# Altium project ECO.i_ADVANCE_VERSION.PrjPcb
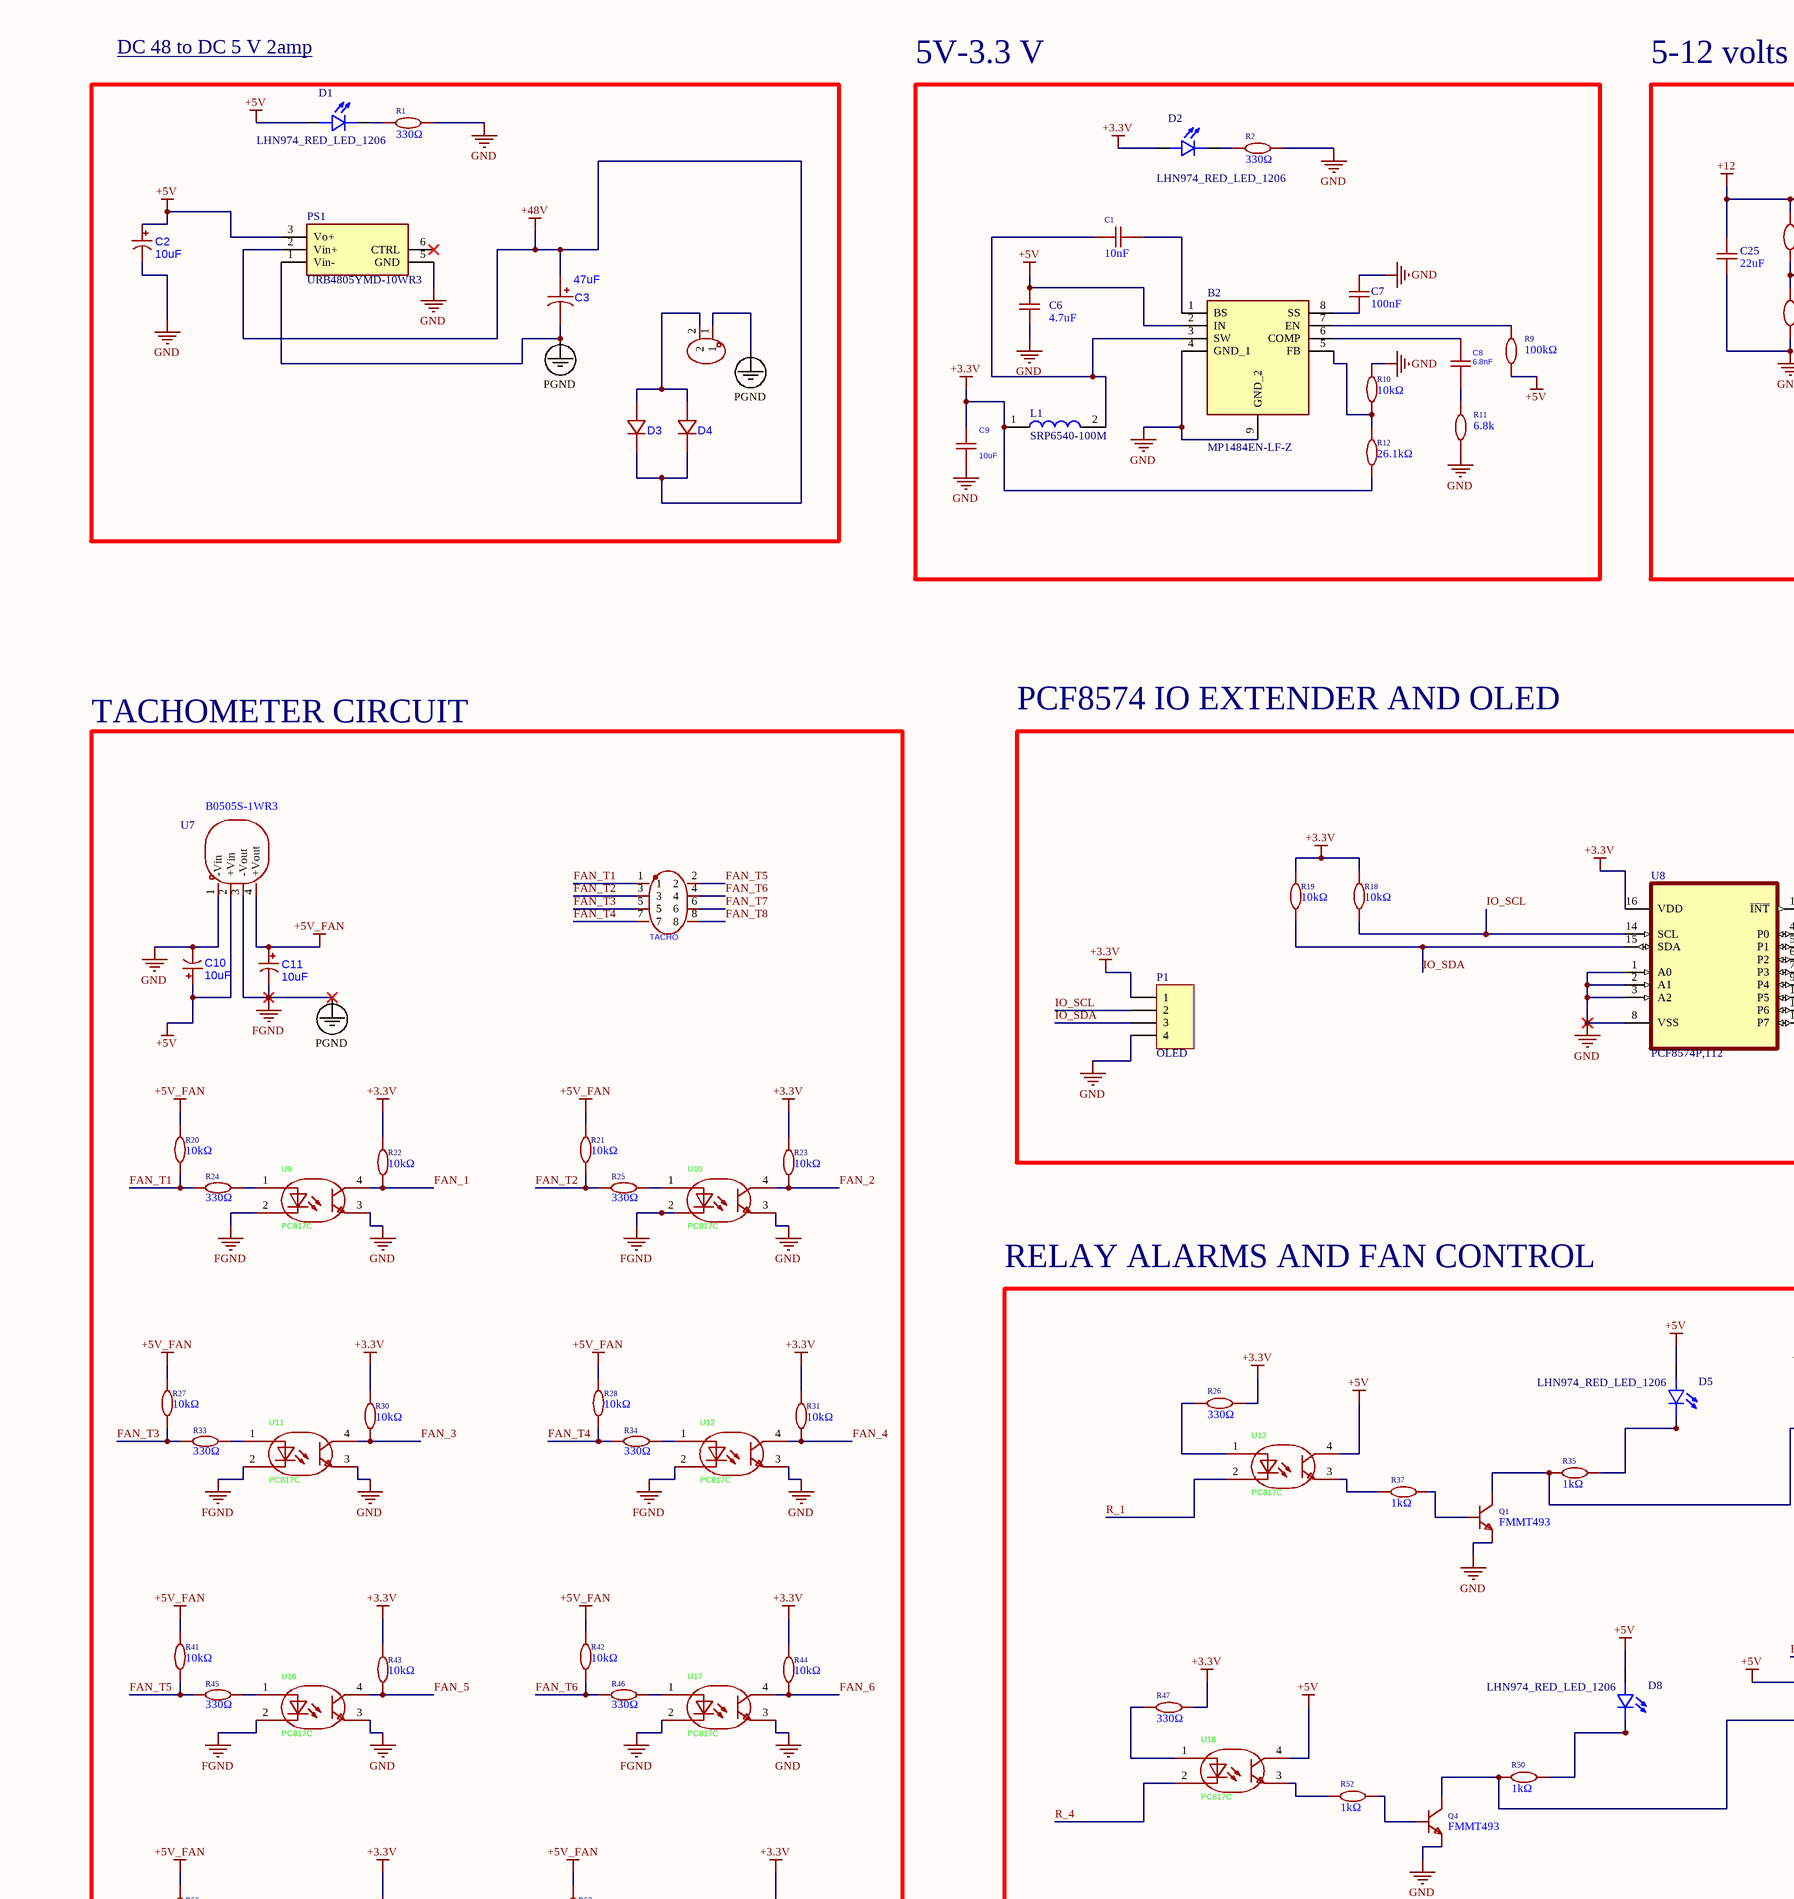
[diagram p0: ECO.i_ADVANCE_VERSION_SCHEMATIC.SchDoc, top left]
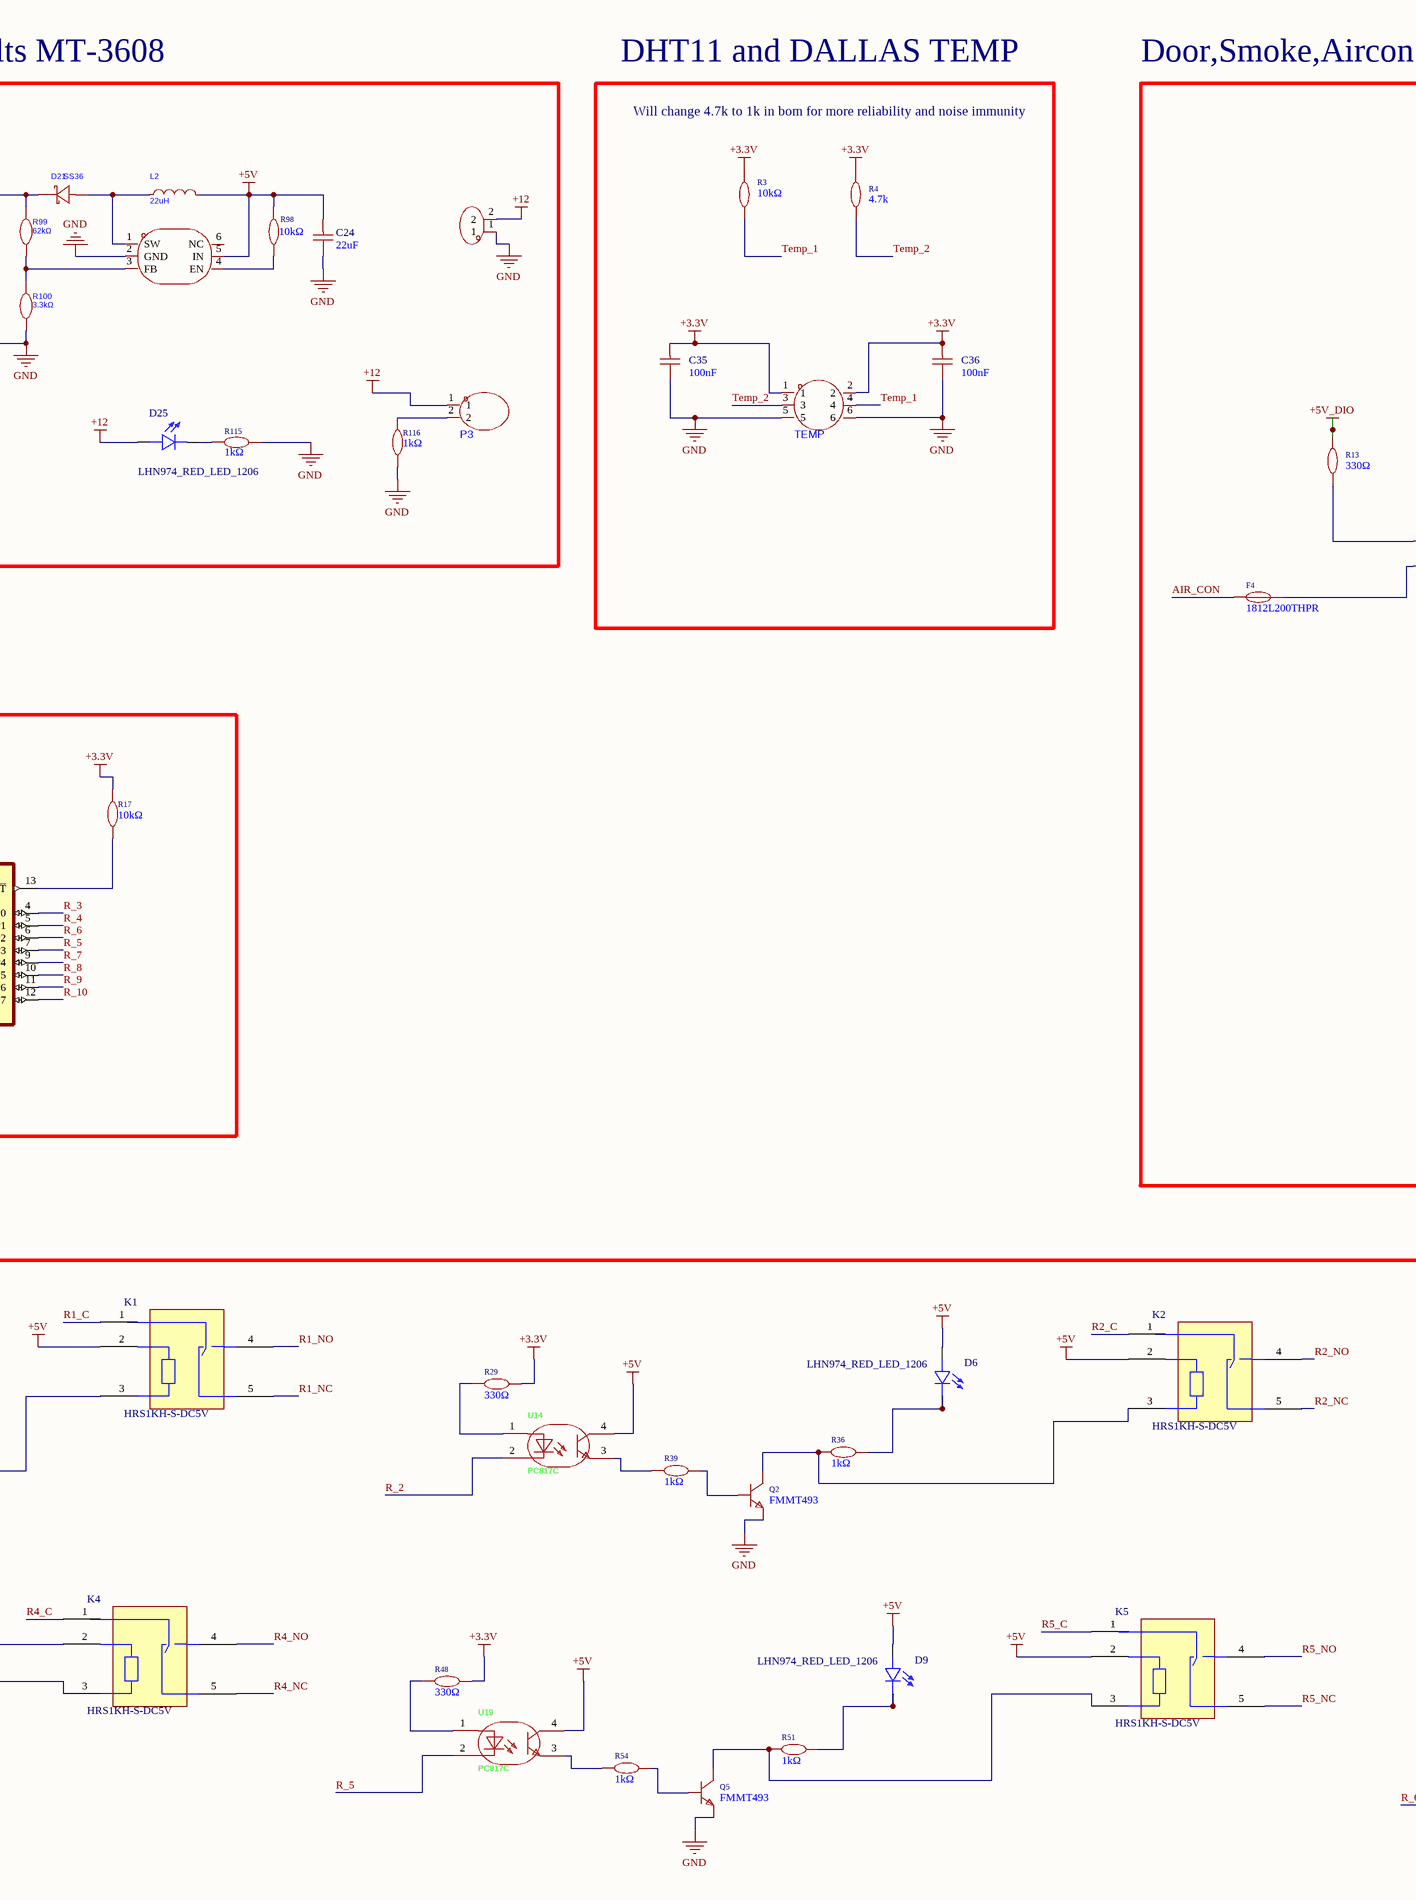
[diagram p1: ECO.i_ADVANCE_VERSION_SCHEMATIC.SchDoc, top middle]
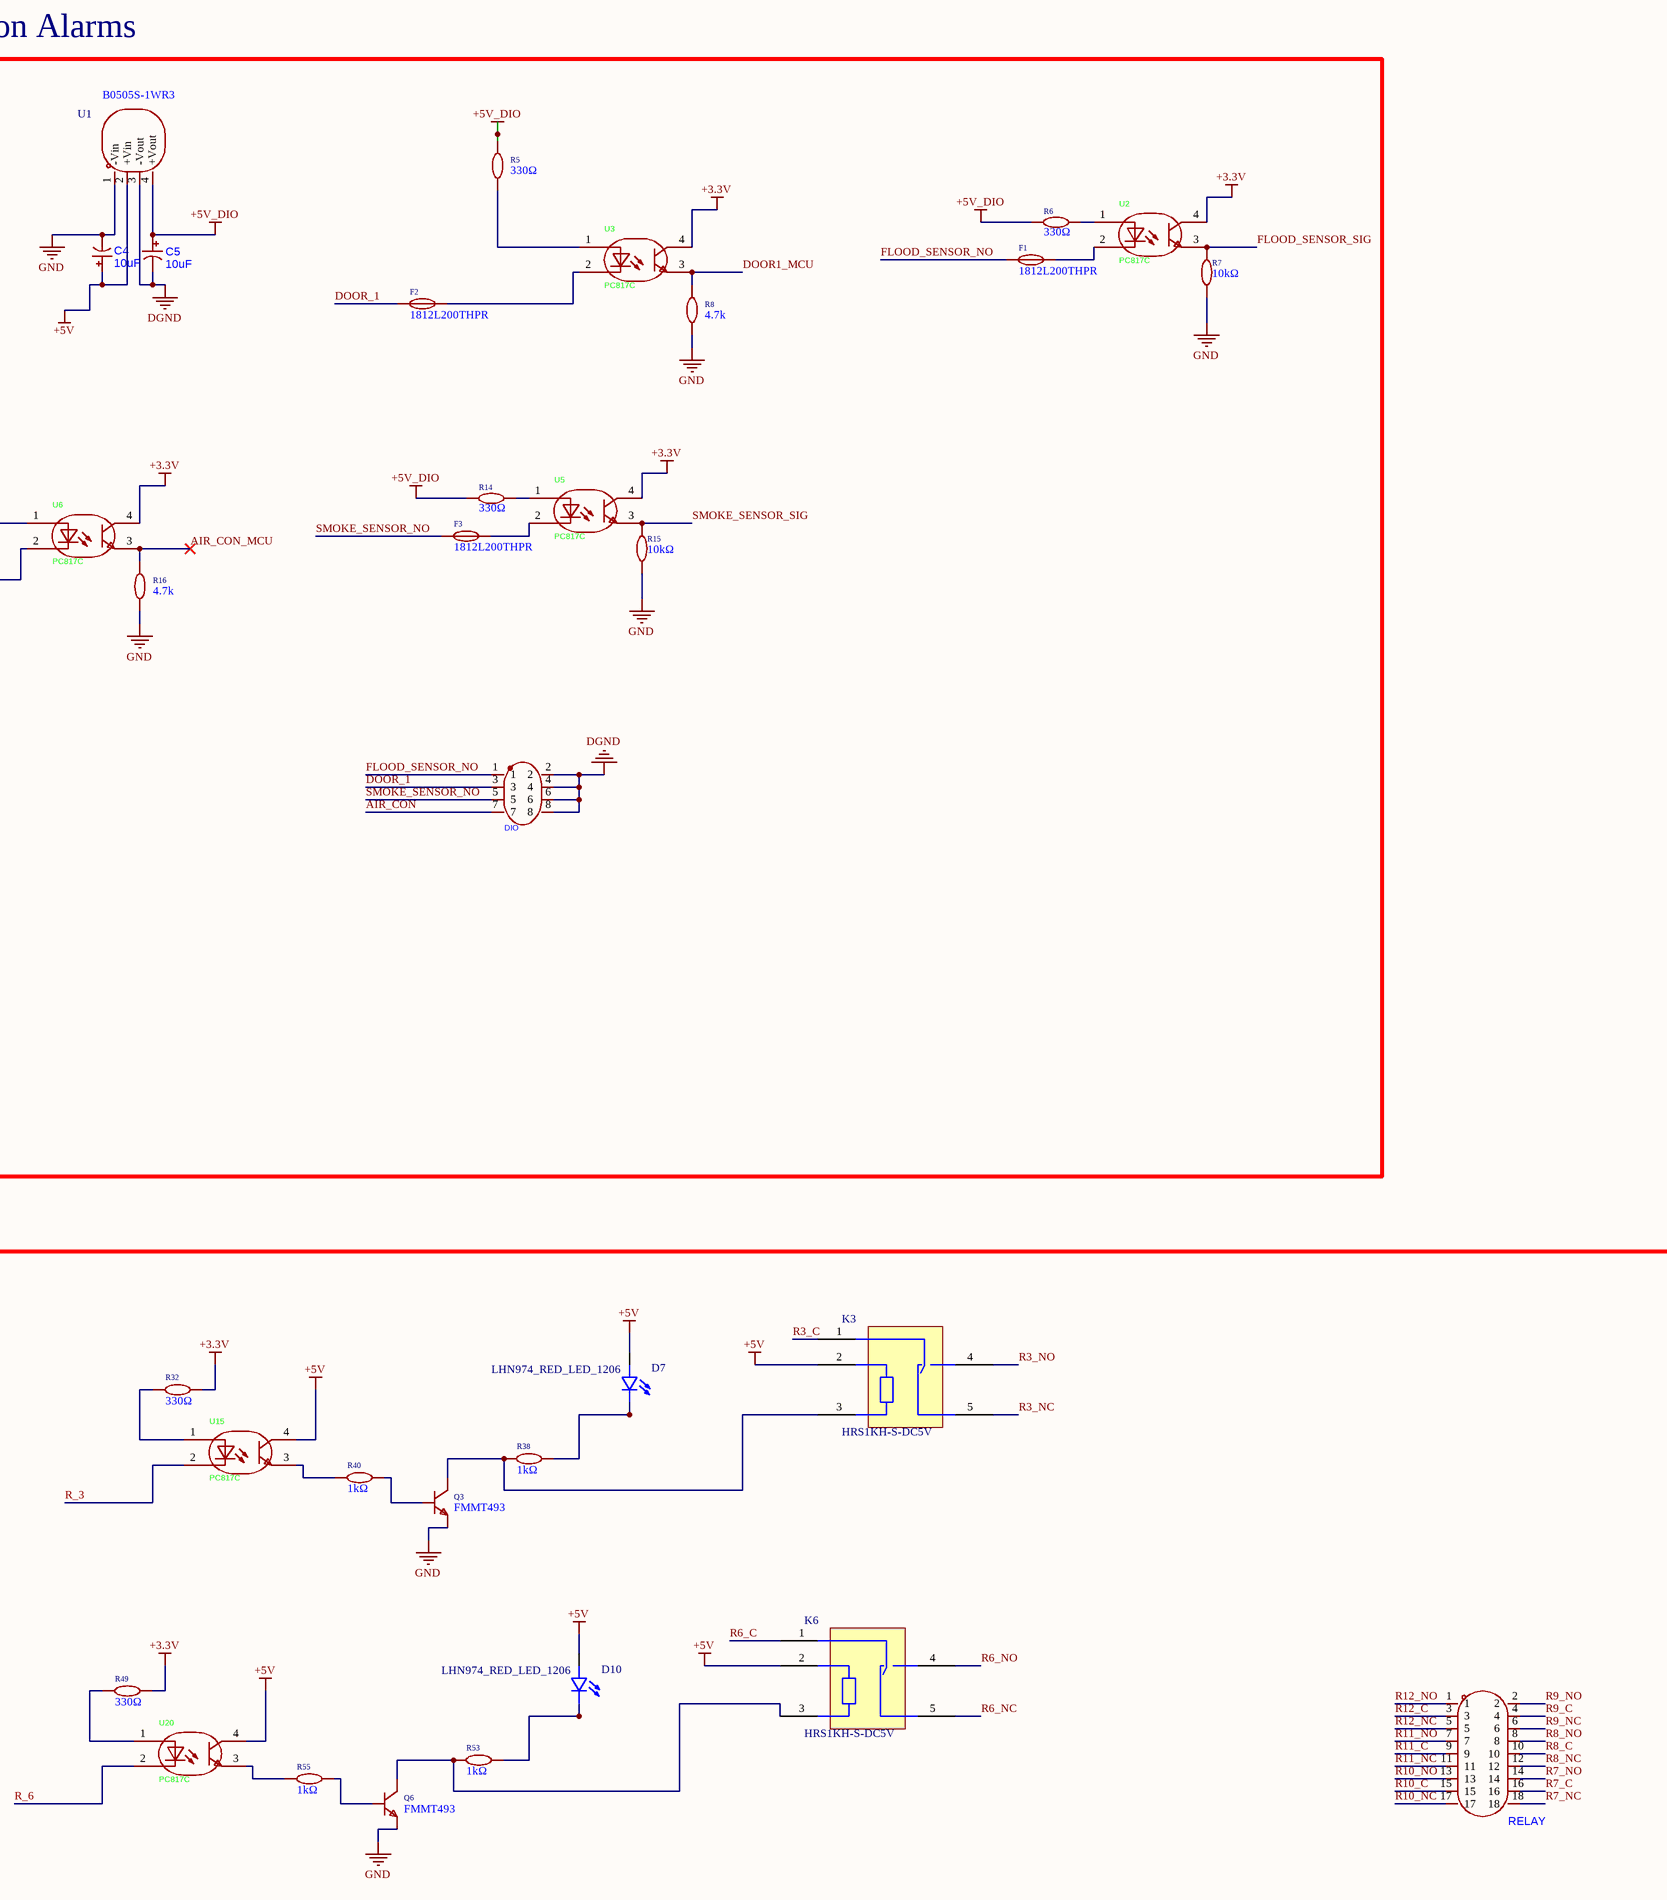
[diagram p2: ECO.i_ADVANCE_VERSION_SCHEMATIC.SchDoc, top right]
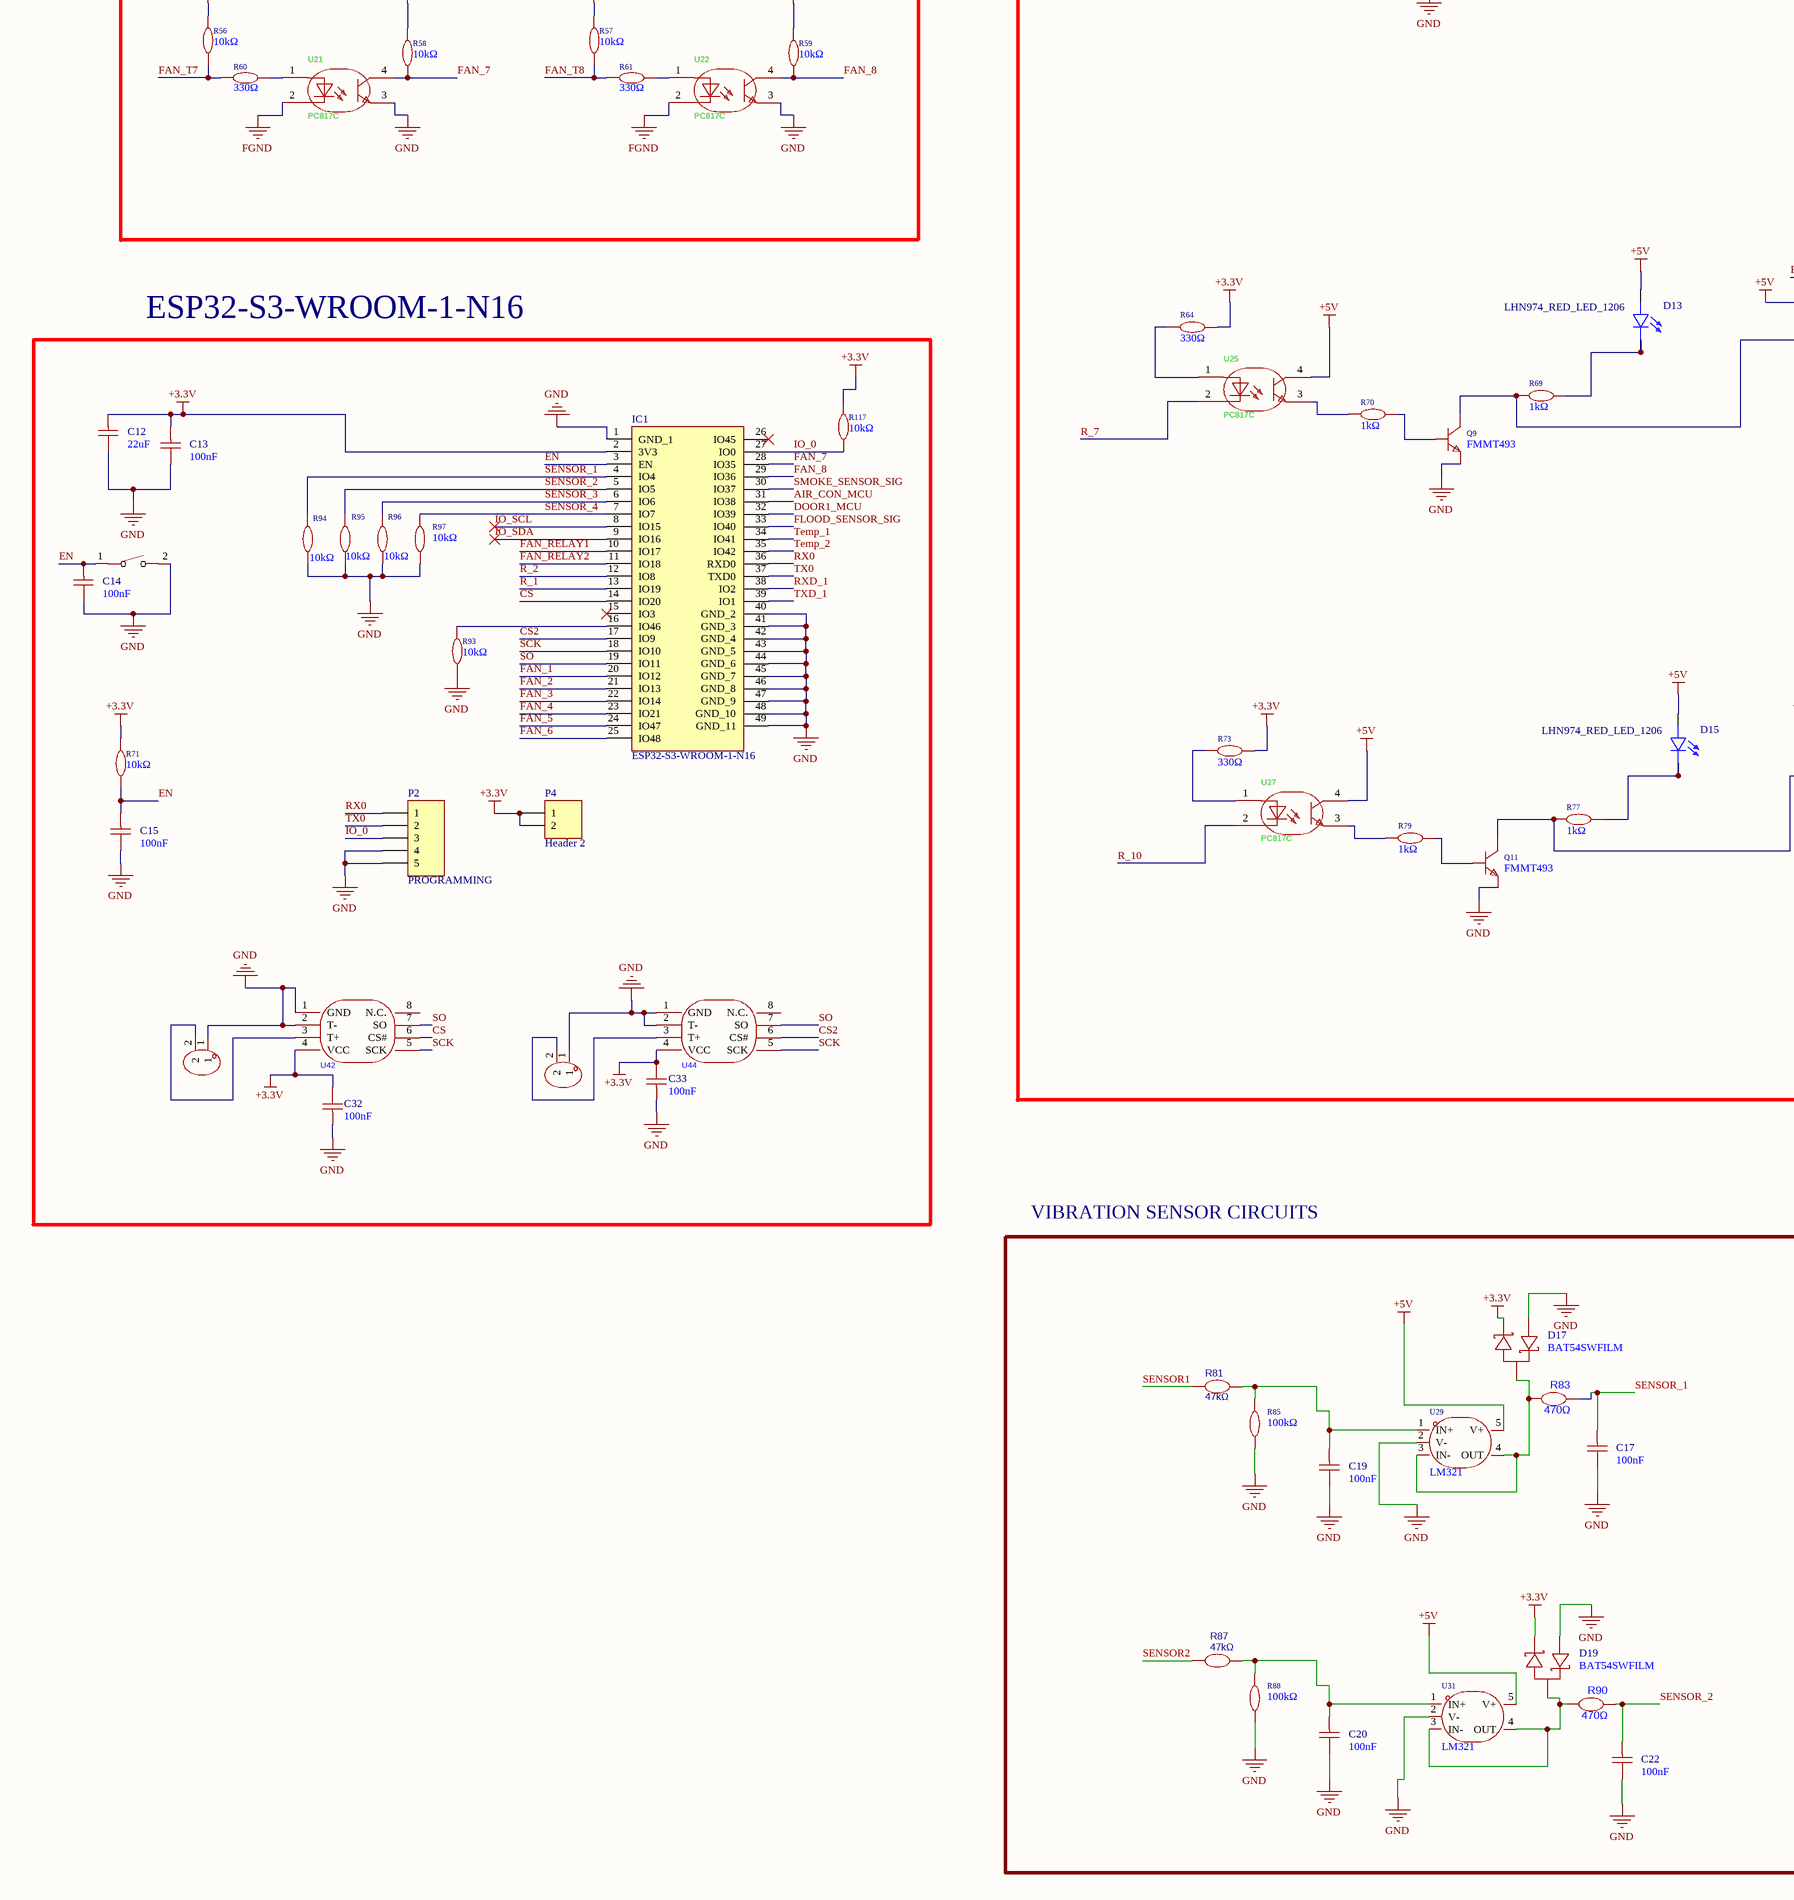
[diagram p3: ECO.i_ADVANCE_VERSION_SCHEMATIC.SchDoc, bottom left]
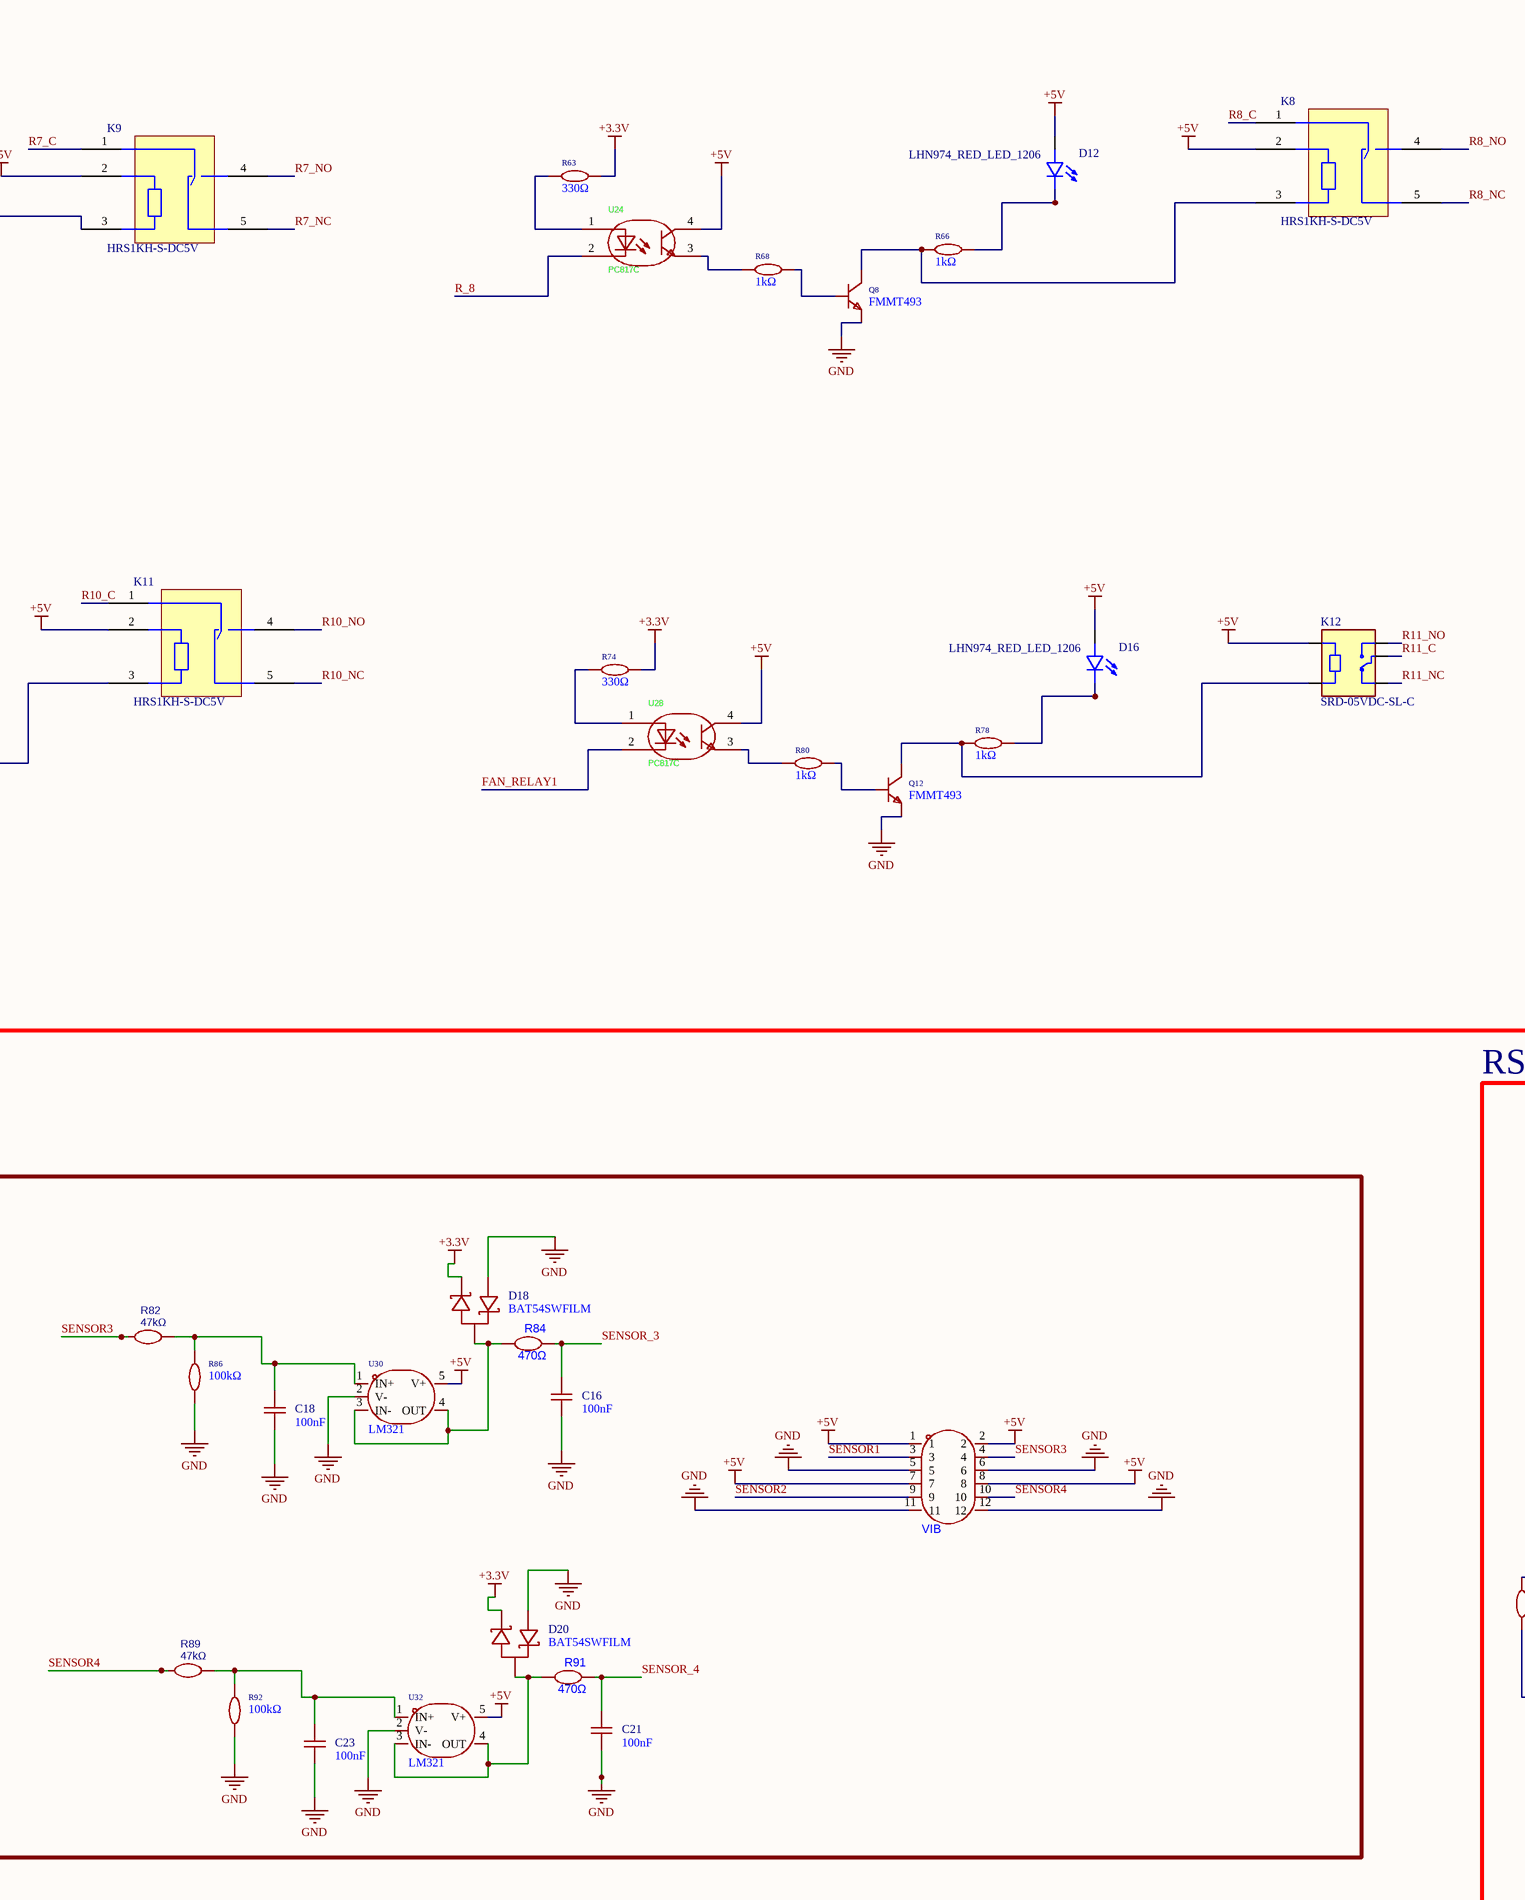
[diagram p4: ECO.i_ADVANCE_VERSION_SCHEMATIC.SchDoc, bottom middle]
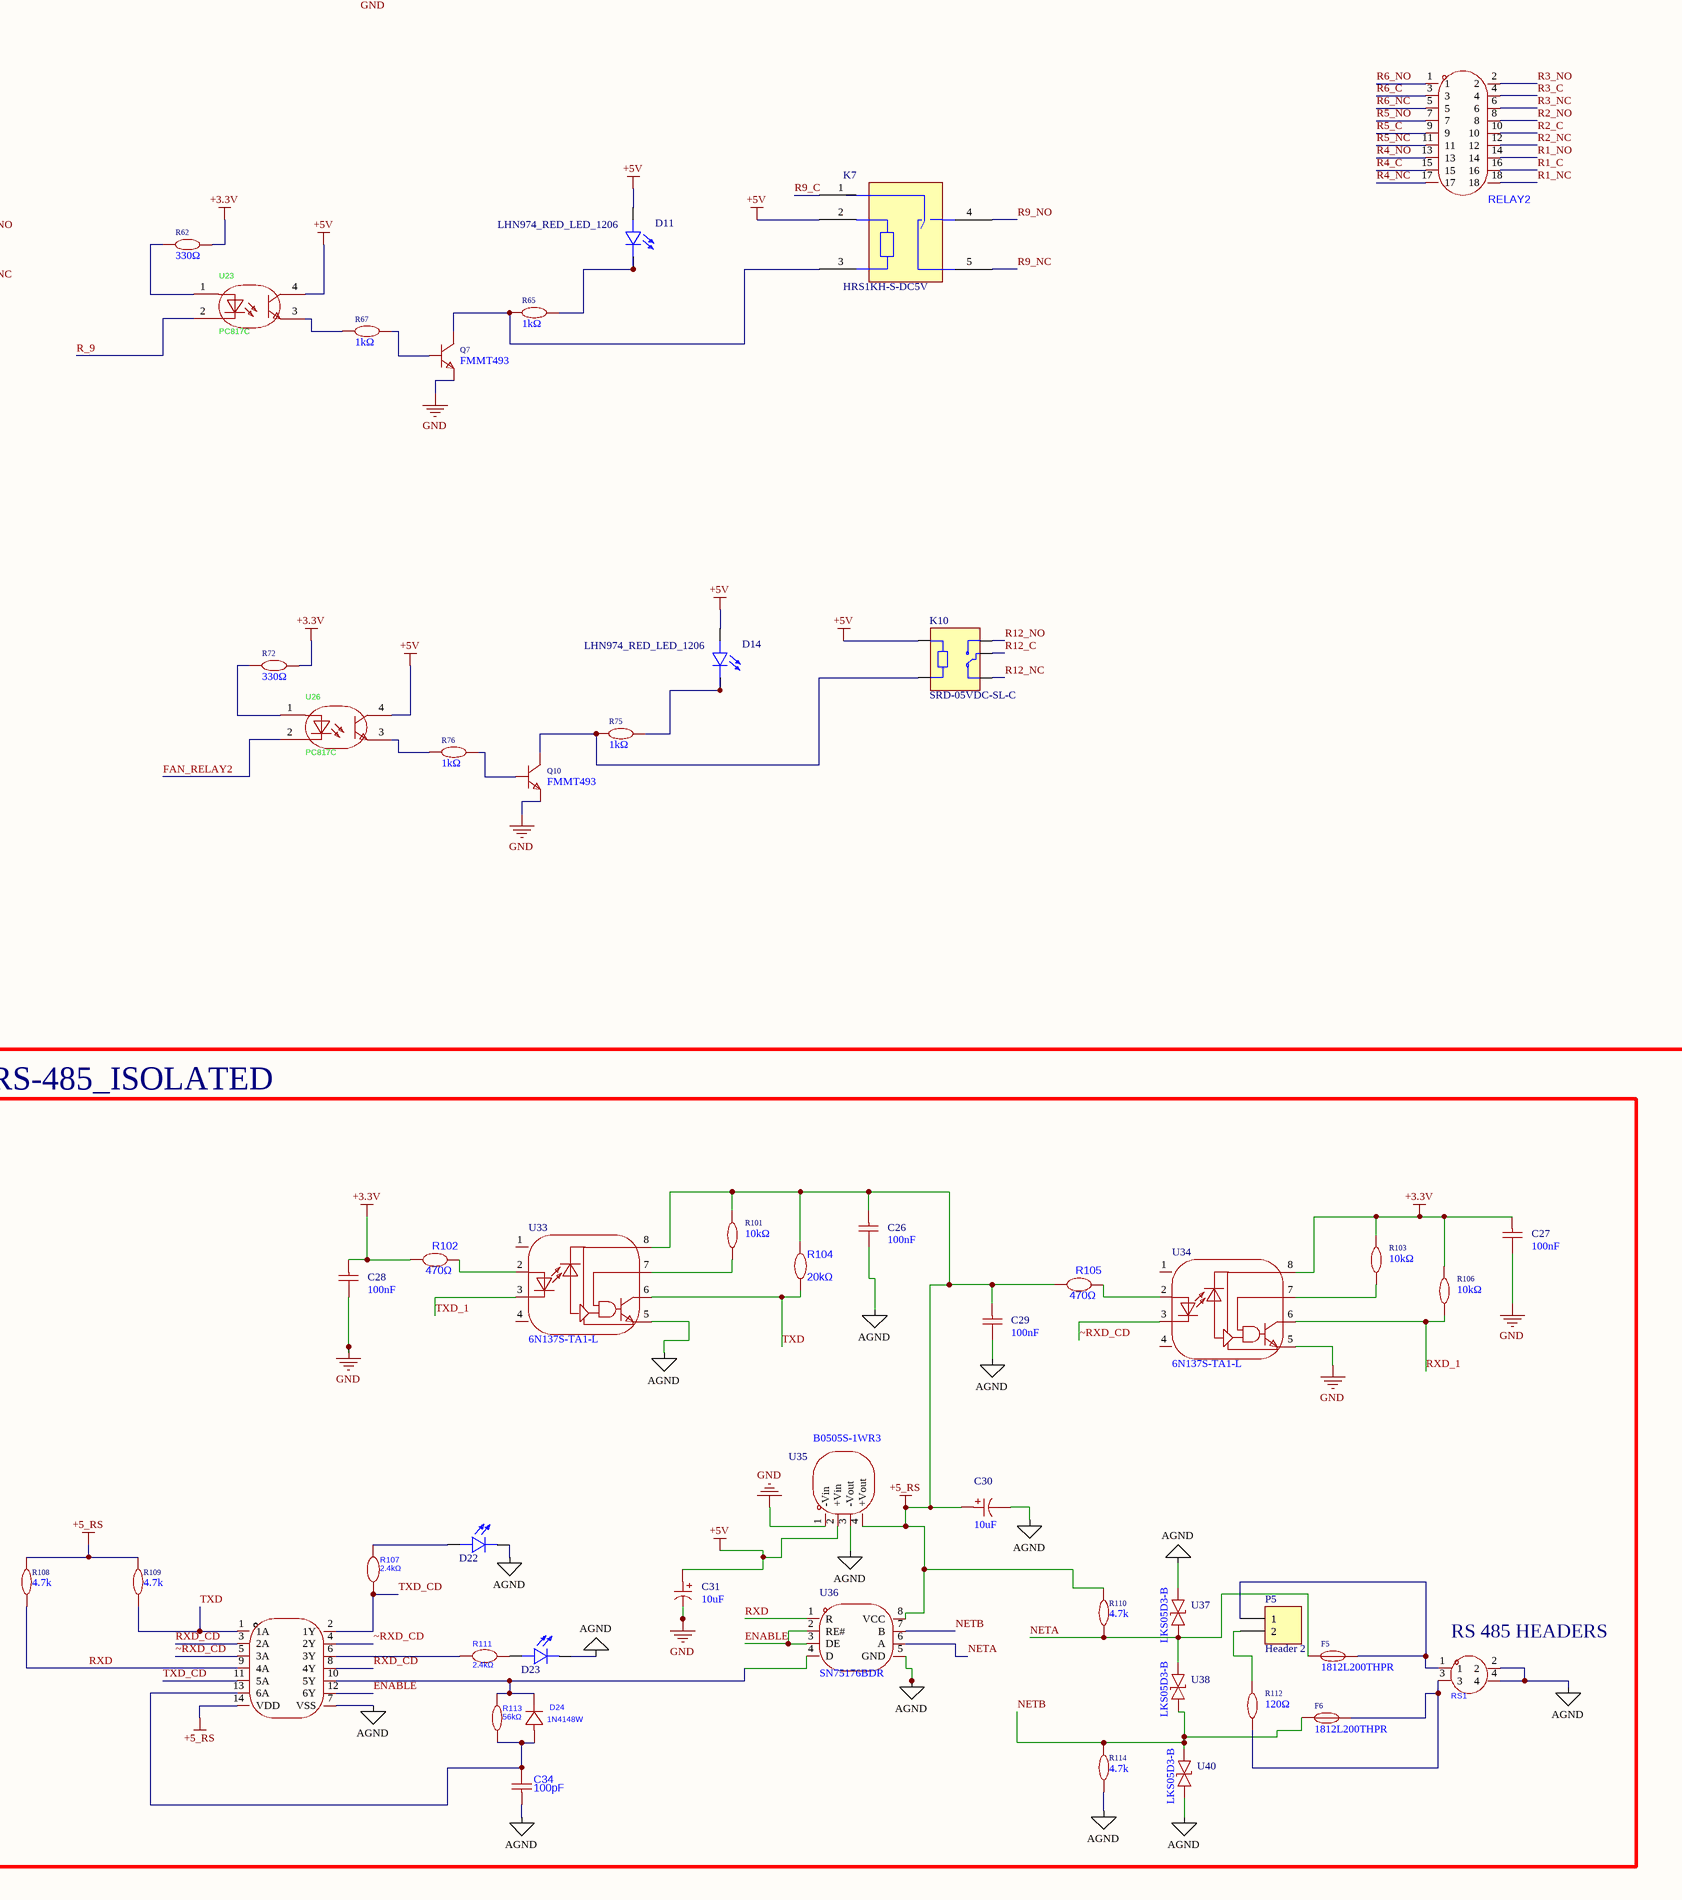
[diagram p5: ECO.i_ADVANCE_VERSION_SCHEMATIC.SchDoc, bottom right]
1 sheet, 272 parts. Net scope: global (net labels, ports and power ports of the same name join across sheets).
Board file: ECO.i_ADVANCE_VERSION_PCB.PcbDoc

## Sheet ECO.i_ADVANCE_VERSION_SCHEMATIC.SchDoc
size E

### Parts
12volts  DB2ERC-3.81-2P-BK  [CONN-TH_2P-P3.81_DB2ERC-3.81-2P-BK]  (value not drawn)
B2  MP1484EN-LF-Z  [SOIC127P600X170-9N]
C1  10nF  [C1206]
C2  10uF  [CAP-SMD_BD4.0-L4.3-W4.3-FD]
C3  47uF  [CAPAE1000X1130N]
C4  10uF  [CAP-SMD_BD4.0-L4.3-W4.3-FD]
C5  10uF  [CAP-SMD_BD4.0-L4.3-W4.3-FD]
C6  4.7uF  [C1206]
C7  100nF  [C1206]
C8  6.8nF  [C1206]
C9  10uF  [C1206]
C10  10uF  [CAP-SMD_BD4.0-L4.3-W4.3-FD]
C11  10uF  [CAP-SMD_BD4.0-L4.3-W4.3-FD]
C12  22uF  [C1206]
C13  100nF  [C1206]
C14  100nF  [C1206]
C15  100nF  [C1206]
C16  100nF  [C1206]
C17  100nF  [C1206]
C18  100nF  [C1206]
C19  100nF  [C1206]
C20  100nF  [C1206]
C21  100nF  [C1206]
C22  100nF  [C1206]
C23  100nF  [C1206]
C24  22uF  [C1206]
C25  22uF  [C1206]
C26  100nF  [C1206]
C27  100nF  [C1206]
C28  100nF  [C1206]
C29  100nF  [C1206]
C30  10uF  [WCAP-ASLI_D5H5.5]
C31  10uF  [WCAP-ASLI_D5H5.5]
C32  100nF  [C1206]
C33  100nF  [C1206]
C34  100pF  [C1206]
C35  100nF  [C1206]
C36  100nF  [C1206]
D1  LHN974_RED_LED_1206  [LEDC3216X120N]
D2  LHN974_RED_LED_1206  [LEDC3216X120N]
D3  RS3MB  [diode_in]  (value not drawn)
D4  RS3MB  [diode_in]  (value not drawn)
D5  LHN974_RED_LED_1206  [LEDC3216X120N]
D6  LHN974_RED_LED_1206  [LEDC3216X120N]
D7  LHN974_RED_LED_1206  [LEDC3216X120N]
D8  LHN974_RED_LED_1206  [LEDC3216X120N]
D9  LHN974_RED_LED_1206  [LEDC3216X120N]
D10  LHN974_RED_LED_1206  [LEDC3216X120N]
D11  LHN974_RED_LED_1206  [LEDC3216X120N]
D12  LHN974_RED_LED_1206  [LEDC3216X120N]
D13  LHN974_RED_LED_1206  [LEDC3216X120N]
D14  LHN974_RED_LED_1206  [LEDC3216X120N]
D15  LHN974_RED_LED_1206  [LEDC3216X120N]
D16  LHN974_RED_LED_1206  [LEDC3216X120N]
D17  BAT54SWFILM  [SOT65P210X110-3N (BAT54SWFILM)]
D18  BAT54SWFILM  [SOT65P210X110-3N (BAT54SWFILM)]
D19  BAT54SWFILM  [SOT65P210X110-3N (BAT54SWFILM)]
D20  BAT54SWFILM  [SOT65P210X110-3N (BAT54SWFILM)]
D21  SS36  [SMA_L4.4-W2.6-LS5.0-RD]
D22  LHN974_RED_LED_1206  [LEDC3216X120N]  (value not drawn)
D23  LHN974_RED_LED_1206  [LEDC3216X120N]  (value not drawn)
D24  1N4148W  [SOD-123_L2.8-W1.8-LS3.7-RD-1]
D25  LHN974_RED_LED_1206  [LEDC3216X120N]
DIO  KF2EDGSR-3.5-2*4P  [CONN-TH_8P-P3.50_KEFA_KF2EDGSR-3.5-2X4P]  (value not drawn)
F1  1812L200THPR  [1812L010DR]
F2  1812L200THPR  [1812L010DR]
F3  1812L200THPR  [1812L010DR]
F4  1812L200THPR  [1812L010DR]
F5  1812L200THPR  [1812L010DR]
F6  1812L200THPR  [1812L010DR]
IC1  ESP32-S3-WROOM-1-N16  [ESP32S3WROOM1N16]
K1  HRS1KH-S-DC5V  [RELAY-TH_HRS1KH-S-DCXXX]
K2  HRS1KH-S-DC5V  [RELAY-TH_HRS1KH-S-DCXXX]
K3  HRS1KH-S-DC5V  [RELAY-TH_HRS1KH-S-DCXXX]
K4  HRS1KH-S-DC5V  [RELAY-TH_HRS1KH-S-DCXXX]
K5  HRS1KH-S-DC5V  [RELAY-TH_HRS1KH-S-DCXXX]
K6  HRS1KH-S-DC5V  [RELAY-TH_HRS1KH-S-DCXXX]
K7  HRS1KH-S-DC5V  [RELAY-TH_HRS1KH-S-DCXXX]
K8  HRS1KH-S-DC5V  [RELAY-TH_HRS1KH-S-DCXXX]
K9  HRS1KH-S-DC5V  [RELAY-TH_HRS1KH-S-DCXXX]
K10  SRD-05VDC-SL-C  [RELAY_SRD-05VDC-SL-C]
K11  HRS1KH-S-DC5V  [RELAY-TH_HRS1KH-S-DCXXX]
K12  SRD-05VDC-SL-C  [RELAY_SRD-05VDC-SL-C]
L1  SRP6540-100M  [SRP6540]
L2  22uH  [IND-SMD_L7.3-W6.6_MHCI06030]
P1  OLED  [HDR1X4]
P2  PROGRAMMING  [HDR1X5]
P3  B2B-XH-A(LF)(SN)  [CONN-TH_B2B-XH-A-LF-SN]  (value not drawn)
P4  Header 2  [HDR1X2]
P5  Header 2  [HDR1X2]
POWER  DB2ERC-3.81-2P-BK  [CONN-TH_2P-P3.81_DB2ERC-3.81-2P-BK]  (value not drawn)
PS1  URB4805YMD-10WR3  [PS1]
Q1  FMMT493  [SOT91P240X120-3N]
Q2  FMMT493  [SOT91P240X120-3N]
Q3  FMMT493  [SOT91P240X120-3N]
Q4  FMMT493  [SOT91P240X120-3N]
Q5  FMMT493  [SOT91P240X120-3N]
Q6  FMMT493  [SOT91P240X120-3N]
Q7  FMMT493  [SOT91P240X120-3N]
Q8  FMMT493  [SOT91P240X120-3N]
Q9  FMMT493  [SOT91P240X120-3N]
Q10  FMMT493  [SOT91P240X120-3N]
Q11  FMMT493  [SOT91P240X120-3N]
Q12  FMMT493  [SOT91P240X120-3N]
R1  330Ω  [RESC3216X75N]
R2  330Ω  [RESC3216X75N]
R3  10kΩ  [RESC3216X75N]
R4  4.7k  [RESC3216X75N]
R5  330Ω  [RESC3216X75N]
R6  330Ω  [RESC3216X75N]
R7  10kΩ  [RESC3216X75N]
R8  4.7k  [RESC3216X75N]
R9  100kΩ  [RESC3216X75N]
R10  10kΩ  [RESC3216X75N]
R11  6.8k  [RESC3216X75N]
R12  26.1kΩ  [RESC3216X75N]
R13  330Ω  [RESC3216X75N]
R14  330Ω  [RESC3216X75N]
R15  10kΩ  [RESC3216X75N]
R16  4.7k  [RESC3216X75N]
R17  10kΩ  [RESC3216X75N]
R18  10kΩ  [RESC3216X75N]
R19  10kΩ  [RESC3216X75N]
R20  10kΩ  [RESC3216X75N]
R21  10kΩ  [RESC3216X75N]
R22  10kΩ  [RESC3216X75N]
R23  10kΩ  [RESC3216X75N]
R24  330Ω  [RESC3216X75N]
R25  330Ω  [RESC3216X75N]
R26  330Ω  [RESC3216X75N]
R27  10kΩ  [RESC3216X75N]
R28  10kΩ  [RESC3216X75N]
R29  330Ω  [RESC3216X75N]
R30  10kΩ  [RESC3216X75N]
R31  10kΩ  [RESC3216X75N]
R32  330Ω  [RESC3216X75N]
R33  330Ω  [RESC3216X75N]
R34  330Ω  [RESC3216X75N]
R35  1kΩ  [RESC3216X75N]
R36  1kΩ  [RESC3216X75N]
R37  1kΩ  [RESC3216X75N]
R38  1kΩ  [RESC3216X75N]
R39  1kΩ  [RESC3216X75N]
R40  1kΩ  [RESC3216X75N]
R41  10kΩ  [RESC3216X75N]
R42  10kΩ  [RESC3216X75N]
R43  10kΩ  [RESC3216X75N]
R44  10kΩ  [RESC3216X75N]
R45  330Ω  [RESC3216X75N]
R46  330Ω  [RESC3216X75N]
R47  330Ω  [RESC3216X75N]
R48  330Ω  [RESC3216X75N]
R49  330Ω  [RESC3216X75N]
R50  1kΩ  [RESC3216X75N]
R51  1kΩ  [RESC3216X75N]
R52  1kΩ  [RESC3216X75N]
R53  1kΩ  [RESC3216X75N]
R54  1kΩ  [RESC3216X75N]
R55  1kΩ  [RESC3216X75N]
R56  10kΩ  [RESC3216X75N]
R57  10kΩ  [RESC3216X75N]
R58  10kΩ  [RESC3216X75N]
R59  10kΩ  [RESC3216X75N]
R60  330Ω  [RESC3216X75N]
R61  330Ω  [RESC3216X75N]
R62  330Ω  [RESC3216X75N]
R63  330Ω  [RESC3216X75N]
R64  330Ω  [RESC3216X75N]
R65  1kΩ  [RESC3216X75N]
R66  1kΩ  [RESC3216X75N]
R67  1kΩ  [RESC3216X75N]
R68  1kΩ  [RESC3216X75N]
R69  1kΩ  [RESC3216X75N]
R70  1kΩ  [RESC3216X75N]
R71  10kΩ  [RESC3216X75N]
R72  330Ω  [RESC3216X75N]
R73  330Ω  [RESC3216X75N]
R74  330Ω  [RESC3216X75N]
R75  1kΩ  [RESC3216X75N]
R76  1kΩ  [RESC3216X75N]
R77  1kΩ  [RESC3216X75N]
R78  1kΩ  [RESC3216X75N]
R79  1kΩ  [RESC3216X75N]
R80  1kΩ  [RESC3216X75N]
R81  47kΩ  [RESC3216X75N]
R82  47kΩ  [R1206]
R83  470Ω  [RESC3216X75N]
R84  470Ω  [RESC3216X75N]
R85  100kΩ  [RESC3216X75N]
R86  100kΩ  [RESC3216X75N]
R87  47kΩ  [R1206]
R88  100kΩ  [RESC3216X75N]
R89  47kΩ  [R1206]
R90  470Ω  [RESC3216X75N]
R91  470Ω  [RESC3216X75N]
R92  100kΩ  [RESC3216X75N]
R93  10kΩ  [RESC3216X75N]
R94  10kΩ  [RESC3216X75N]
R95  10kΩ  [RESC3216X75N]
R96  10kΩ  [RESC3216X75N]
R97  10kΩ  [RESC3216X75N]
R98  10kΩ  [RESC3216X75N]
R99  62kΩ  [RESC3216X75N]
R100  3.3kΩ  [RESC3216X75N]
R101  10kΩ  [RESC3216X75N]
R102  470Ω  [RESC3216X75N]
R103  10kΩ  [RESC3216X75N]
R104  20kΩ  [RESC3216X75N]
R105  470Ω  [RESC3216X75N]
R106  10kΩ  [RESC3216X75N]
R107  2.4kΩ  [RESC3216X75N]
R108  4.7k  [RESC3216X75N]
R109  4.7k  [RESC3216X75N]
R110  4.7k  [RESC3216X75N]
R111  2.4kΩ  [RESC3216X75N]
R112  120Ω  [RESC3216X75N]
R113  56kΩ  [RESC3216X75N]
R114  4.7k  [RESC3216X75N]
R115  1kΩ  [RESC3216X75N]
R116  1kΩ  [RESC3216X75N]
R117  10kΩ  [RESC3216X75N]
RELAY  KF2EDGSR-3.5-2*9P  [CONN-TH_18P-P3.50_KEFA_KF2EDGSR-3.5-2X9P]  (value not drawn)
RELAY2  KF2EDGSR-3.5-2*9P  [CONN-TH_18P-P3.50_KEFA_KF2EDGSR-3.5-2X9P]  (value not drawn)
RS1  KF2EDGSR-3.5-2*2P  [CONN-TH_4P-P3.50_KEFA_KF2EDGSR-3.5-2X2P]  (value not drawn)
SW1  TS-1088-AR02016  [SW-SMD_L3.9-W3.0-P4.45]  (value not drawn)
TACHO  KF2EDGSR-3.5-2*4P  [CONN-TH_8P-P3.50_KEFA_KF2EDGSR-3.5-2X4P]  (value not drawn)
TEMP  KF2EDGSR-3.5-2*3P  [CONN-TH_6P-P3.50_KEFA_KF2EDGSR-3.5-2X3P]  (value not drawn)
U1  B0505S-1WR3  [TME0512S]
U2  PC817C  [DIP762W60P254L460H455Q4N]
U3  PC817C  [DIP762W60P254L460H455Q4N]
U4  MT3608  [SOT-23-6_L2.9-W1.6-P0.95-LS2.8-BL]  (value not drawn)
U5  PC817C  [DIP762W60P254L460H455Q4N]
U6  PC817C  [DIP762W60P254L460H455Q4N]
U7  B0505S-1WR3  [TME0512S]
U8  PCF8574P,112  [DIP254P762X420-16]
U9  PC817C  [DIP762W60P254L460H455Q4N]
U10  PC817C  [DIP762W60P254L460H455Q4N]
U11  PC817C  [DIP762W60P254L460H455Q4N]
U12  PC817C  [DIP762W60P254L460H455Q4N]
U13  PC817C  [DIP762W60P254L460H455Q4N]
U14  PC817C  [DIP762W60P254L460H455Q4N]
U15  PC817C  [DIP762W60P254L460H455Q4N]
U16  PC817C  [DIP762W60P254L460H455Q4N]
U17  PC817C  [DIP762W60P254L460H455Q4N]
U18  PC817C  [DIP762W60P254L460H455Q4N]
U19  PC817C  [DIP762W60P254L460H455Q4N]
U20  PC817C  [DIP762W60P254L460H455Q4N]
U21  PC817C  [DIP762W60P254L460H455Q4N]
U22  PC817C  [DIP762W60P254L460H455Q4N]
U23  PC817C  [DIP762W60P254L460H455Q4N]
U24  PC817C  [DIP762W60P254L460H455Q4N]
U25  PC817C  [DIP762W60P254L460H455Q4N]
U26  PC817C  [DIP762W60P254L460H455Q4N]
U27  PC817C  [DIP762W60P254L460H455Q4N]
U28  PC817C  [DIP762W60P254L460H455Q4N]
U29  LM321  [SOT95P280X145-5N]
U30  LM321  [SOT95P280X145-5N]
U31  LM321  [SOT95P280X145-5N]
U32  LM321  [SOT95P280X145-5N]
U33  6N137S-TA1-L  [6N137S-TA1-L]
U34  6N137S-TA1-L  [6N137S-TA1-L]
U35  B0505S-1WR3  [TME0512S]
U36  SN75176BDR  [SOIC127P599X175-8N]
U37  LKS05D3-B  [TVS DIODE]
U38  LKS05D3-B  [TVS DIODE]
U39  CD4069  [SOP-14_L8.8-W3.9-P1.27-LS6.0-BL]  (value not drawn)
U40  LKS05D3-B  [TVS DIODE]
U41  DBT30R-7.62-2P-BK-P  [CONN-TH_2P-P7.62_DBT30R-7.62-2P]  (value not drawn)
U42  MAX6675ISA+T  [SOIC-8_L5.0-W4.0-P1.27-LS6.0-BL]  (value not drawn)
U43  DBT30R-7.62-2P-BK-P  [CONN-TH_2P-P7.62_DBT30R-7.62-2P]  (value not drawn)
U44  MAX6675ISA+T  [SOIC-8_L5.0-W4.0-P1.27-LS6.0-BL]  (value not drawn)
VIB  KF2EDGSR-3.5-2*6P  [CONN-TH_12P-P3.50_KEFA_KF2EDGSR-3.5-2X6P]  (value not drawn)

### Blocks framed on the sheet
5V-3.3 V: B2 C1 C6-C9 D2 L1 R2 R9-R12
5-12 volts MT-3608: 12volts C24 C25 D21 D25 L2 P3 R98-R100 R115 R116 U4
DHT11 and DALLAS TEMP: C35 C36 R3 R4 TEMP
Door,Smoke,Aircon Alarms: C4 C5 DIO F1-F4 R5-R8 R13-R16 U1-U3 U5 U6
TACHOMETER CIRCUIT: C10 C11 R20-R25 R27 R28 R30 R31 R33 R34 R41-R46 R56-R61 TACHO U7 U9-U12 U16 U17 U21 U22
PCF8574 IO EXTENDER AND OLED: P1 R17-R19 U8
RELAY ALARMS AND FAN CONTROL: D5-D16 K1-K12 Q1-Q12 R26 R29 R32 R35-R40 R47-R55 R62-R70 R72-R80 RELAY RELAY2 U13-U15 U18-U20 U23-U28
ESP32-S3-WROOM-1-N16: C12-C15 C32 C33 IC1 P2 P4 R71 R93-R97 R117 SW1 U41-U44
RS-485_ISOLATED: C26-C31 C34 D22-D24 F5 F6 P5 R101-R114 RS1 U33-U40
VIBRATION SENSOR CIRCUITS: C16-C23 D17-D20 R81-R92 U29-U32 VIB

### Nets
+3.3V: C9.2 C12.1 C13.1 C27.1 C28.1 C32.2 C33.2 C35.1 C36.1 D2.POS D17.2 D18.2 D19.2 D20.2 IC1.2(3V3) L1.1 P1.1 P4.1 P4.2 R3.2 R4.2 R12.2 R17.1 R18.2 R19.2 R22.1 R23.1 R26.2 R29.2 R30.1 R31.1 R32.2 R43.1 R44.1 R47.2 R48.2 R49.2 R58.1 R59.1 R62.2 R63.2 R64.2 R71.1 R72.2 R73.2 R74.2 R102.1 R103.2 R106.2 R117.2 TEMP.1 TEMP.2 U2.4(COLLECTOR) U3.4(COLLECTOR) U5.4(COLLECTOR) U6.4(COLLECTOR) U8.16(VDD) U34.8 U42.4(VCC) U44.4(VCC)
+5_RS: C26.1 C29.1 C30.1 R101.2 R104.2 R105.1 R108.1 R109.1 R110.1 U33.8 U35.4(+Vout) U36.8(VCC) U39.14(VDD)
+5V: B2.2(IN) C2.1 C4.1 C6.1 C10.1 C24.1 C31.1 D1.POS D5.POS D6.POS D7.POS D8.POS D9.POS D10.POS D11.POS D12.POS D13.POS D14.POS D15.POS D16.POS K1.2 K2.2 K3.2 K4.2 K5.2 K6.2 K7.2 K8.2 K9.2 K10.A1 K11.2 K12.A1 L2.2 PS1.3(Vo+) R9.1 R98.2 U1.2(+Vin) U4.5(IN) U7.2(+Vin) U13.4(COLLECTOR) U14.4(COLLECTOR) U15.4(COLLECTOR) U18.4(COLLECTOR) U19.4(COLLECTOR) U20.4(COLLECTOR) U23.4(COLLECTOR) U24.4(COLLECTOR) U25.4(COLLECTOR) U26.4(COLLECTOR) U27.4(COLLECTOR) U28.4(COLLECTOR) U29.5(V+) U30.5(V+) U31.5(V+) U32.5(V+) U35.2(+Vin) VIB.1 VIB.2 VIB.7 VIB.8
+5V_DIO: C5.1 R5.2 R6.2 R13.2 R14.2 U1.4(+Vout)
+5V_FAN: C11.1 R20.1 R21.1 R27.1 R28.1 R41.1 R42.1 R56.1 R57.1 U7.4(+Vout)
+12: 12volts.2 C25.1 D21.1(K) D25.POS P3.1 R99.2
+48V: C3.1 D3.1(K) D4.1(K) PS1.2(Vin+)
AGND: C26.2 C29.2 C30.2 C34.1 D22.NEG D23.NEG R114.2 RS1.2 RS1.4 U33.5 U35.3(-Vout) U36.5(GND) U37.2(A) U39.7(VSS) U40.1(K)
DGND: C5.2 DIO.2 DIO.4 DIO.6 DIO.8 U1.3(-Vout)
FGND: C3.2 C11.2 POWER.1 PS1.1(Vin-) U7.3(-Vout) U9.2(C) U10.2(C) U11.2(C) U12.2(C) U16.2(C) U17.2(C) U21.2(C) U22.2(C)  [also labelled PGND]
GND: 12volts.1 B2.4(GND_1) B2.9(GND_2) C2.2 C4.2 C6.2 C7.2 C9.1 C10.2 C12.2 C13.2 C14.2 C15.2 C16.2 C17.2 C18.2 C19.2 C20.2 C21.2 C22.2 C23.2 C24.2 C25.2 C27.2 C28.2 C31.2 C32.1 C33.1 C35.2 C36.2 D17.1 D18.1 D19.1 D20.1 IC1.1(GND_1) IC1.40(GND_2) IC1.41(GND_3) IC1.42(GND_4) IC1.43(GND_5) IC1.44(GND_6) IC1.45(GND_7) IC1.46(GND_8) IC1.47(GND_9) IC1.48(GND_10) IC1.49(GND_11) P1.4 P2.4 P2.5 PS1.5(GND) Q1.2(E) Q2.2(E) Q3.2(E) Q4.2(E) Q5.2(E) Q6.2(E) Q7.2(E) Q8.2(E) Q9.2(E) Q10.2(E) Q11.2(E) Q12.2(E) R1.2 R2.2 R7.1 R8.1 R10.1 R11.1 R15.1 R16.1 R85.1 R86.1 R88.1 R92.1 R93.2 R94.1 R95.1 R96.1 R97.1 R100.1 R115.1 R116.2 SW1.2 TEMP.5 TEMP.6 U1.1(-Vin) U4.2(GND) U7.1(-Vin) U8.1(A0) U8.2(A1) U8.3(A2) U8.8(VSS) U9.3(E) U10.3(E) U11.3(E) U12.3(E) U16.3(E) U17.3(E) U21.3(E) U22.3(E) U29.2(V-) U30.2(V-) U31.2(V-) U32.2(V-) U34.5 U35.1(-Vin) U41.1 U42.1(GND) U42.2(T-) U43.1 U44.1(GND) U44.2(T-) VIB.5 VIB.6 VIB.11 VIB.12
AIR_CON: DIO.7 F4.1
AIR_CON_MCU: IC1.31(IO38) R16.2 U6.3(E)
CS: IC1.14(IO20) U42.6(CS#)
CS2: IC1.17(IO9) U44.6(CS#)
DOOR1_MCU: IC1.32(IO39) R8.2 U3.3(E)
DOOR_1: DIO.3 F2.1
EN: C14.1 C15.1 IC1.3(EN) R71.2 SW1.1
ENABLE: U36.2(RE#) U36.3(DE) U39.12(6Y)
FAN_1: IC1.20(IO12) R22.2 U9.4(COLLECTOR)
FAN_2: IC1.21(IO13) R23.2 U10.4(COLLECTOR)
FAN_3: IC1.22(IO14) R30.2 U11.4(COLLECTOR)
FAN_4: IC1.23(IO21) R31.2 U12.4(COLLECTOR)
FAN_5: IC1.24(IO47) R43.2 U16.4(COLLECTOR)
FAN_6: IC1.25(IO48) R44.2 U17.4(COLLECTOR)
FAN_7: IC1.28(IO35) R58.2 U21.4(COLLECTOR)
FAN_8: IC1.29(IO36) R59.2 U22.4(COLLECTOR)
FAN_RELAY1: IC1.10(IO17) U28.2(C)
FAN_RELAY2: IC1.11(IO18) U26.2(C)
FAN_T1: R20.2 R24.2 TACHO.1
FAN_T2: R21.2 R25.2 TACHO.3
FAN_T3: R27.2 R33.2 TACHO.5
FAN_T4: R28.2 R34.2 TACHO.7
FAN_T5: R41.2 R45.2 TACHO.2
FAN_T6: R42.2 R46.2 TACHO.4
FAN_T7: R56.2 R60.2 TACHO.6
FAN_T8: R57.2 R61.2 TACHO.8
FLOOD_SENSOR_NO: DIO.1 F1.1
FLOOD_SENSOR_SIG: IC1.33(IO40) R7.2 U2.3(E)
IO_0: IC1.27(IO0) P2.3 R117.1
IO_SCL: IC1.8(IO15) P1.2 R18.1 U8.14(SCL)
IO_SDA: IC1.9(IO16) P1.3 R19.1 U8.15(SDA)
NETA: F5.1 R110.2 U36.6(A) U37.1(K) U38.2(A)
NETB: F6.1 R114.1 U36.7(B) U38.1(K) U40.2(A)
R1_C: K1.1 RELAY2.16
R1_NC: K1.5 RELAY2.18
R1_NO: K1.4 RELAY2.14
R2_C: K2.1 RELAY2.10
R2_NC: K2.5 RELAY2.12
R2_NO: K2.4 RELAY2.8
R3_C: K3.1 RELAY2.4
R3_NC: K3.5 RELAY2.6
R3_NO: K3.4 RELAY2.2
R4_C: K4.1 RELAY2.15
R4_NC: K4.5 RELAY2.17
R4_NO: K4.4 RELAY2.13
R5_C: K5.1 RELAY2.9
R5_NC: K5.5 RELAY2.11
R5_NO: K5.4 RELAY2.7
R6_C: K6.1 RELAY2.3
R6_NC: K6.5 RELAY2.5
R6_NO: K6.4 RELAY2.1
R7_C: K9.1 RELAY.16
R7_NC: K9.5 RELAY.18
R7_NO: K9.4 RELAY.14
R8_C: K8.1 RELAY.10
R8_NC: K8.5 RELAY.12
R8_NO: K8.4 RELAY.8
R9_C: K7.1 RELAY.4
R9_NC: K7.5 RELAY.6
R9_NO: K7.4 RELAY.2
R10_C: K11.1 RELAY.15
R10_NC: K11.5 RELAY.17
R10_NO: K11.4 RELAY.13
R11_C: K12.COM RELAY.9
R11_NC: K12.NC RELAY.11
R11_NO: K12.NO RELAY.7
R12_C: K10.COM RELAY.3
R12_NC: K10.NC RELAY.5
R12_NO: K10.NO RELAY.1
R_1: IC1.13(IO19) U13.2(C)
R_2: IC1.12(IO8) U14.2(C)
R_3: U8.4(P0) U15.2(C)
R_4: U8.5(P1) U18.2(C)
R_5: U8.7(P3) U19.2(C)
R_6: U8.6(P2) U20.2(C)
R_7: U8.9(P4) U25.2(C)
R_8: U8.10(P5) U24.2(C)
R_9: U8.11(P6) U23.2(C)
R_10: U8.12(P7) U27.2(C)
RX0: IC1.36(RXD0) P2.1
RXD: R108.2 U36.1(R) U39.9(4A)
RXD_1: IC1.38(IO2) R106.1 U34.6
RXD_CD: U39.3(2A) U39.8(4Y)
SCK: IC1.18(IO10) U42.5(SCK) U44.5(SCK)
SENSOR1: R81.2 VIB.3
SENSOR2: R87.1 VIB.9
SENSOR3: R82.1 VIB.4
SENSOR4: R89.1 VIB.10
SENSOR_1: C17.1 IC1.4(IO4) R83.2 R94.2
SENSOR_2: C22.1 IC1.5(IO5) R90.2 R95.2
SENSOR_3: C16.1 IC1.6(IO6) R84.2 R96.2
SENSOR_4: C21.1 IC1.7(IO7) R91.2 R97.2
SMOKE_SENSOR_NO: DIO.5 F3.1
SMOKE_SENSOR_SIG: IC1.30(IO37) R15.2 U5.3(E)
SO: IC1.19(IO11) U42.7(SO) U44.7(SO)
Temp_1: IC1.34(IO41) R3.1 TEMP.4
Temp_2: IC1.35(IO42) R4.1 TEMP.3
TX0: IC1.37(TXD0) P2.2
TXD: R104.1 R109.2 U33.6 U39.1(1A)
TXD_1: IC1.39(IO1) U33.3
TXD_CD: R107.1 U39.2(1Y) U39.11(5A)
~RXD_CD: U34.3 U39.4(2Y) U39.5(3A)
NetB2_1: B2.1(BS) C1.1
NetB2_3: B2.3(SW) C1.2 L1.2
NetB2_5: B2.5(FB) R10.2 R12.1
NetB2_6: B2.6(COMP) C8.1
NetB2_7: B2.7(EN) R9.2
NetB2_8: B2.8(SS) C7.1
NetC8_2: C8.2 R11.2
NetC18_1: C18.1 R82.2 R86.2 U30.1(IN+)
NetC19_1: C19.1 R81.1 R85.2 U29.1(IN+)
NetC20_1: C20.1 R87.2 R88.2 U31.1(IN+)
NetC23_1: C23.1 R89.2 R92.2 U32.1(IN+)
NetC34_2: C34.2 D24.2(A) R113.2 U39.13(6A)
NetD1_NEG: D1.NEG R1.1
NetD2_NEG: D2.NEG R2.1
NetD3_2: D3.2(A) D4.2(A) POWER.2
NetD5_NEG: D5.NEG R35.2
NetD6_NEG: D6.NEG R36.2
NetD7_NEG: D7.NEG R38.2
NetD8_NEG: D8.NEG R50.2
NetD9_NEG: D9.NEG R51.2
NetD10_NEG: D10.NEG R53.2
NetD11_NEG: D11.NEG R65.2
NetD12_NEG: D12.NEG R66.2
NetD13_NEG: D13.NEG R69.2
NetD14_NEG: D14.NEG R75.2
NetD15_NEG: D15.NEG R77.2
NetD16_NEG: D16.NEG R78.2
NetD17_3: D17.3 R83.1 U29.3(IN-) U29.4(OUT)
NetD18_3: D18.3 R84.1 U30.3(IN-) U30.4(OUT)
NetD19_3: D19.3 R90.1 U31.3(IN-) U31.4(OUT)
NetD20_3: D20.3 R91.1 U32.3(IN-) U32.4(OUT)
NetD21_2: D21.2(A) L2.1 U4.1(SW)
NetD22_POS: D22.POS R107.2
NetD23_POS: D23.POS R111.1
NetD24_1: D24.1(C) R113.1 U36.4(D) U39.10(5Y)
NetD25_NEG: D25.NEG R115.2
NetF1_2: F1.2 U2.2(C)
NetF2_2: F2.2 U3.2(C)
NetF3_2: F3.2 U5.2(C)
NetF4_2: F4.2 U6.2(C)
NetF5_2: F5.2 P5.1 RS1.1
NetF6_2: F6.2 R112.1 RS1.3
NetIC1_16: IC1.16(IO46) R93.1
NetK1_3: K1.3 Q1.3(C) R35.1
NetK2_3: K2.3 Q2.3(C) R36.1
NetK3_3: K3.3 Q3.3(C) R38.1
NetK4_3: K4.3 Q4.3(C) R50.1
NetK5_3: K5.3 Q5.3(C) R51.1
NetK6_3: K6.3 Q6.3(C) R53.1
NetK7_3: K7.3 Q7.3(C) R65.1
NetK8_3: K8.3 Q8.3(C) R66.1
NetK9_3: K9.3 Q9.3(C) R69.1
NetK10_A2: K10.A2 Q10.3(C) R75.1
NetK11_3: K11.3 Q11.3(C) R77.1
NetK12_A2: K12.A2 Q12.3(C) R78.1
NetP3_2: P3.2 R116.1
NetP5_2: P5.2 R112.2
NetQ1_1: Q1.1(B) R37.2
NetQ2_1: Q2.1(B) R39.2
NetQ3_1: Q3.1(B) R40.2
NetQ4_1: Q4.1(B) R52.2
NetQ5_1: Q5.1(B) R54.2
NetQ6_1: Q6.1(B) R55.2
NetQ7_1: Q7.1(B) R67.2
NetQ8_1: Q8.1(B) R68.2
NetQ9_1: Q9.1(B) R70.2
NetQ10_1: Q10.1(B) R76.2
NetQ11_1: Q11.1(B) R79.2
NetQ12_1: Q12.1(B) R80.2
NetR5_1: R5.1 U3.1(A)
NetR6_1: R6.1 U2.1(A)
NetR13_1: R13.1 U6.1(A)
NetR14_1: R14.1 U5.1(A)
NetR17_2: R17.2 U8.13(~{INT})
NetR24_1: R24.1 U9.1(A)
NetR25_1: R25.1 U10.1(A)
NetR26_1: R26.1 U13.1(A)
NetR29_1: R29.1 U14.1(A)
NetR32_1: R32.1 U15.1(A)
NetR33_1: R33.1 U11.1(A)
NetR34_1: R34.1 U12.1(A)
NetR37_1: R37.1 U13.3(E)
NetR39_1: R39.1 U14.3(E)
NetR40_1: R40.1 U15.3(E)
NetR45_1: R45.1 U16.1(A)
NetR46_1: R46.1 U17.1(A)
NetR47_1: R47.1 U18.1(A)
NetR48_1: R48.1 U19.1(A)
NetR49_1: R49.1 U20.1(A)
NetR52_1: R52.1 U18.3(E)
NetR54_1: R54.1 U19.3(E)
NetR55_1: R55.1 U20.3(E)
NetR60_1: R60.1 U21.1(A)
NetR61_1: R61.1 U22.1(A)
NetR62_1: R62.1 U23.1(A)
NetR63_1: R63.1 U24.1(A)
NetR64_1: R64.1 U25.1(A)
NetR67_1: R67.1 U23.3(E)
NetR68_1: R68.1 U24.3(E)
NetR70_1: R70.1 U25.3(E)
NetR72_1: R72.1 U26.1(A)
NetR73_1: R73.1 U27.1(A)
NetR74_1: R74.1 U28.1(A)
NetR76_1: R76.1 U26.3(E)
NetR79_1: R79.1 U27.3(E)
NetR80_1: R80.1 U28.3(E)
NetR98_1: R98.1 U4.4(EN)
NetR99_1: R99.1 R100.2 U4.3(FB)
NetR101_1: R101.1 U33.7
NetR102_2: R102.2 U33.2
NetR103_1: R103.1 U34.7
NetR105_2: R105.2 U34.2
NetR111_2: R111.2 U39.6(3Y)
NetU41_2: U41.2 U42.3(T+)
NetU43_2: U43.2 U44.3(T+)

Not connected (* = marked no-connect by the designer): IC1 15(IO3)* 26(IO45)*; PS1 6(CTRL)*; U4 6(NC); U33 1 4; U34 1 4; U42 8(N.C.); U44 8(N.C.)

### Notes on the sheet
- DC 48 to DC 5 V 2amp <https://www.aimtec.com/site/Aimtec/files/Datasheet/HighResolution/am10cw-nz.pdf?ft4=9-475>
- Will change 4.7k to 1k in bom for more reliability and noise immunity
- (near RS1) RS 485 HEADERS

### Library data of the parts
12volts POWER = DB2ERC-3.81-2P-BK_C5259145: Manufacturer: DORABO(地博电气); Add into BOM: yes; Number of Positions or Pins: 1x2P; Pitch: 3.81mm; Number of PINs Per Row: 2; Current Rating: 8A; Voltage Rating (Max): 300V
B2 = MP1484EN-LF-Z: Switching Voltage Regulators 3A, 18V Sync Step-Down DCDC; Manufacturer_Name: Monolithic Power Systems (MPS)
C1 = CC1206FKNPO8BN103: Manufacturer: YAGEO(国巨); Add into BOM: yes; Tolerance: ±1%
C2 C4 C5 C10 C11 = RVT1E100M0405: Manufacturer: HONOR(荣誉); Add into BOM: yes; Tolerance: ±20%; Voltage Rating: 25V; Lifetime: 2000hrs@105℃
C3 = GVZ2A476M1010CNVC: Manufacturer: HRK(鸿瑞凯电子); Add into BOM: yes; Tolerance: ±20%; Voltage Rating: 100V; Ripple Current: 200mA@100kHz; Equivalent Series Resistance(ESR): 700mΩ@100kHz; Lifetime: 2000hrs@105℃
C6 C7 C13-C23 C26-C29 C32 C33 C35 C36 = 1206B104K500NT: Manufacturer: FH(风华); Add into BOM: yes; Tolerance: ±10%
C8 = CC1206JRNPO9BN682: Manufacturer: YAGEO(国巨); Add into BOM: yes; Tolerance: ±5%
C9 = CL31A106KBHNNNE: Manufacturer: SAMSUNG(三星); Add into BOM: yes; Tolerance: ±10%
C12 C24 C25 = 1206B104K500NT: Manufacturer: FH(风华); Manufacturer Part: 1206X226M250NT1206B104K500NT; Symbol: 1206X226M250NT; Add into BOM: yes; Tolerance: ±10%
C30 C31 = RVT10UF25V67RV0020: Manufacturer: KNSCHA(科尼盛); Add into BOM: yes; Tolerance: ±20%; Ripple Current: 21mA@120Hz; Lifetime @ Temp: 2000hrs@105℃
C34 = CC1206JKNPOCBN101: Manufacturer: YAGEO(国巨); Add into BOM: yes; Tolerance: ±5%
D1 D2 D5-D16 D22 D23 D25 = LHN974_RED_LED_1206: 2.6 V Red LED SMD; MF: Osram; MP: LHN974 RED LED 1206
D3 D4 = RS3MB_C2766054: Manufacturer: WPMtek(维攀); Add into BOM: yes; Voltage - Forward(Vf@If): 1.3V@3A; Voltage - DC Reverse(Vr): 1kV; Current - Rectified: 3A; Reverse Leakage Current (Ir): 5uA@1000V; Reverse Recovery Time (trr): 500ns
D17-D20 = BAT54SWFILM: Manufacturer: ST(意法半导体); Add into BOM: yes; Diode Configuration: 1对串联式; Forward Voltage (Vf@If): 900mV@100mA; Reverse Voltage (Vr): 40V; Average Rectified Current (Io): 300mA; Reverse Leakage Current (Ir): 1uA@30V
D21 = SS36_C727061: Manufacturer: TWGMC(台湾迪嘉); Add into BOM: yes; Diode Configuration: Independent; Voltage - Forward(Vf@If): 700mV@3A; Voltage - DC Reverse(Vr): 60V; Current - Rectified: 3A; Reverse Leakage Current (Ir): 500uA; Operating Junction Temperature Range: -55℃~+125℃
D24 = 1N4148W_C917030: Manufacturer: JSMSEMI(杰盛微); Add into BOM: yes; Diode Configuration: Independent; Voltage - Forward(Vf@If): 1.25V@150mA; Voltage - DC Reverse(Vr): 100V; Current - Rectified: 300mA; Pd - Power Dissipation: 400mW; Reverse Leakage Current (Ir): 1uA@75V; Reverse Recovery Time (trr): 8ns; Operating Junction Temperature Range: -55℃~+150℃@(Tj); Non-Repetitive Peak Forward Surge Current: 4A
DIO TACHO = KF2EDGSR-3.5-2*4P: Manufacturer: KEFA(科发); Add into BOM: yes; Connector Type: Receptacle-Close; Structure: 2x4P; Pitch: 3.5mm; Number of PINs Per Row: 4; Current Rating (Max): 10A; Voltage Rating (Max): 300V
F1-F6 = 1812L200THPR: Manufacturer: Littelfuse(美国力特); Add into BOM: yes; Operating Voltage (Max): 8V; Current Rating (Max): 100A; Hold Current: 2A; Trip Current: 3.5A; Resistance - Initial (Ri) (Min): 20mΩ; Resistance - Post Trip (R1) (Max): 70mΩ; Maximum Time to Trip: 2s
IC1 = ESP32-S3-WROOM-1-N16: Integrated Circuit; Manufacturer_Name: Espressif Systems
K10 K12 = SRD-05VDC-SL-C: 5V Trigger Relay Module For Arduino And Raspberry Pi 5V Trigger Relay Module For Arduino And Raspberry Pi; MF: Songle Relay
L1 = SRP6540-100M: Inductor
L2 = SMMS0630-220M: Manufacturer: SXN(顺翔诺); Add into BOM: yes; Tolerance: ±20%; Current - Saturation(Isat): 3.5A; DC Resistance(DCR): 135mΩ
P1 = Header 4: Header, 4-Pin
P2 = Header 5: Header, 5-Pin
P3 = B2B-XH-A(LF)(SN): Manufacturer: JST; Add into BOM: yes; Pins Structure: 1x2P; Pitch: 2.5mm; Reference Series: XH; Number of PINs Per Row: 2; Current Rating: 3A; Voltage Rating: 250V; Plastic Material: PA66; Flame Retardant Rating: UL94V-0; Supplementary Features: K Pin; Z-Height of the Board: 7mm; X-Length of Bottom Edge on Board (Spacing Line): 7.4mm; Y-Width of Bottom Edge on Board: 5.75mm
P4 P5 = Header 2: Header, 2-Pin
PS1 = AM10CW-4805S-NZ_1: Power Supply
Q1-Q12 = FMMT493_C686649: Manufacturer: PJSEMI(平晶微); Add into BOM: yes; DC Current Gain (hFE@Ic,Vce): 300; Transition Frequency (fT): 150MHz; Collector Cut-Off Current (Icbo): 100nA; Collector-Emitter Saturation Voltage (VCE(sat)@Ic,Ib): 600mV@1A,100mA
R1 R2 R5 R6 R13 R14 R24-R26 R29 R32-R34 R45-R49 R60-R64 R72-R74 = 1206W4J0331T5E: Manufacturer: UNI-ROYAL(厚声); Add into BOM: yes; Tolerance: ±5%; Temperature Coefficient: ±100ppm/℃
R3 R7 R10 R15 R17-R23 R27 R28 R30 R31 R41-R44 R56-R59 R71 R93-R98 R101 R103 R106 R117 = 1206W4F1002T5E: Manufacturer: UNI-ROYAL(厚声); Add into BOM: yes; Tolerance: ±1%; Temperature Coefficient: ±100ppm/℃
R4 R8 R16 R108-R110 R114 = 1206W4J0331T5E: Manufacturer: UNI-ROYAL(厚声); Manufacturer Part: 1206W4J0472T5E; Add into BOM: yes; Tolerance: ±5%; Temperature Coefficient: ±100ppm/℃
R9 R11 R85 R86 R88 R92 = 1206W4F1003T5E: Manufacturer: UNI-ROYAL(厚声); Add into BOM: yes; Tolerance: ±1%; Temperature Coefficient: ±100ppm/℃
R12 = 1206W4F1003T5E: Manufacturer: UNI-ROYAL(厚声); Value: 26.1k; Add into BOM: yes; Tolerance: ±1%; Temperature Coefficient: ±100ppm/℃
R35-R40 R50-R55 R65-R70 R75-R80 R115 R116 = 1206W4F1001T5E_C4410: Manufacturer: UNI-ROYAL(厚声); Add into BOM: yes; Tolerance: ±1%
R81 R82 R87 R89 = 47kΩ: Manufacturer: FOJAN(富捷); Manufacturer Part: FRC1206J473 TS; nameAlias: Value; Contributor: lcsc
R83 R84 R90 R91 R102 R105 = FRC1206J471TS: Manufacturer: FOJAN(富捷); Add into BOM: yes; Tolerance: ±5%; Power(Watts): 250mW; Voltage-Supply(Max): 200V; Temperature Coefficient: ±100ppm/℃
R99 = FRC1206F6202TS: Manufacturer: FOJAN(富捷); Add into BOM: yes; Tolerance: ±1%; Power(Watts): 250mW; Voltage-Supply(Max): 200V; Temperature Coefficient: ±100ppm/℃
R100 = FRC1206F3301TS: Manufacturer: FOJAN(富捷); Add into BOM: yes; Tolerance: ±1%; Power(Watts): 250mW; Voltage-Supply(Max): 200V; Temperature Coefficient: ±100ppm/℃
R104 = FRC1206F2002TS: Manufacturer: FOJAN(富捷); Add into BOM: yes; Tolerance: ±1%; Power(Watts): 250mW; Voltage-Supply(Max): 200V; Temperature Coefficient: ±100ppm/℃
R107 R111 = FRC1206F2401TS: Manufacturer: FOJAN(富捷); Add into BOM: yes; Tolerance: ±1%; Power(Watts): 250mW; Voltage-Supply(Max): 200V; Temperature Coefficient: ±100ppm/℃
R112 = 1206W4F1200T5E_C17909: Manufacturer: UNI-ROYAL(厚声); Add into BOM: yes; Tolerance: ±1%; Temperature Coefficient: ±100ppm/℃
R113 = RC1206FR-0756KL: Manufacturer: YAGEO(国巨); Add into BOM: yes; Tolerance: ±1%; Power(Watts): 250mW; Temperature Coefficient: ±100ppm/℃
RELAY RELAY2 = KF2EDGSR-3.5-2*9P: Manufacturer: KEFA(科发); Add into BOM: yes; Connector Type: Receptacle-Close; Structure: 2x9P; Pitch: 3.5mm; Number of PINs Per Row: 9; Current Rating (Max): 10A; Voltage Rating (Max): 300V
RS1 = KF2EDGSR-3.5-2*2P: Manufacturer: KEFA(科发); Add into BOM: yes; Connector Type: Receptacle-Close; Structure: 2x2P; Pitch: 3.5mm; Number of PINs Per Row: 2; Current Rating (Max): 10A; Voltage Rating (Max): 300V
SW1 = TS-1088-AR02016: Manufacturer: XUNPU(讯普); Add into BOM: yes; Circuit: SPST; Actuator Style: Round Button; Operating Force: 160gf; Switch Length: 4mm; Switch Width: 3mm; Switch Height: 2mm; Strike Gundam: 不带; Contact Current: 50mA; Voltage Rating (DC): 12V; Insulation Resistance: 100MΩ; Actuator/Cap Color: Black; Pin Style: SMDSplicing; Mechanical Life: 10万次
TEMP = KF2EDGSR-3.5-2*3P: Manufacturer: KEFA(科发); Add into BOM: yes; Connector Type: Board Side/Socket - Closed; Number of Positions or Pins: 2x3P; Pitch: 3.5mm; Number of PINs Per Row: 3; Current Rating: 10A; Voltage Rating (Max): 300V
U1 U7 U35 = B0505S-1WR3_C7465178: Manufacturer: EVISUN(易成); Add into BOM: yes; Number of channel: 1; Power: 1W; input voltage (Vdc): 4.5V~5.5V; Conversion Efficiency: 86%; Output Voltage: 5V; Output Current (Max): 200mA; Maximum Capacitive Load: 2400uF; Insulated Voltage: 1.5kV
U2 U3 U5 U6 U9-U28 = PC817C_C302516: Manufacturer: AOTE(奥特); Symbol: PC817C_C20612594; Add into BOM: yes; Input voltage type: DC; Forward Voltage: 1.4V; Output Current: 50mA; Isolation Voltage(rms): 5kV; Reverse Voltage: 6V; Number of Outputs: 1; Collector-Emitter Saturation Voltage (Vce(sat)@Ic,IF): 200mV@1mA,20mA
U4 = MT3608: Manufacturer: 西安航天民芯; Add into BOM: yes; Function: Boost; Output Type: Adjustable; Voltage - Supply: 2V~24V; Output Current: 2A; Frequency - Switching: 1.2MHz; Synchronous Rectifier: No; Number of Outputs: 1; Quiescent Current: 100uA；1.6mA; Switch tube (built-in/external): Built-in
U8 = PCF8574P,112: Remote 8-bit I/O expander for I2C-bus; MP: PCF8574P-112
U29-U32 = LM321_C880719: Manufacturer: Slkor(萨科微); Add into BOM: yes; Common Mode Rejection Ratio (CMRR): 90dB; Slew Rate(SR): 0.4V/us
U33 U34 = 6N137S-TA1-L: Manufacturer: LITEON(光宝); Add into BOM: yes; Input Type: DC; Supply Voltage: 4.5V~5.5V; Common Mode Transient Immunity (CMTI): 10kV/us; Data Rate: 15Mbit/s; Propagation Delay tpLH/tpHL: 32ns；40ns; Number of Channels: 1
U36 = SN75176BDR_C7063: Manufacturer: TI(德州仪器); Add into BOM: yes; Types: transceiver; Supply Voltage: 4.75V~5.25V; Driver/receiver: 1/1
U37 U38 U40 = LKS05D3-B: Manufacturer: LANKE(兰科); Add into BOM: yes; Reverse Stand-Off Voltage (Vrwm): 5V@Max; Maximum Clamping Voltage: 12V@Typ; Peak Pulse Current (Ipp)@10/1000us: 40A@8/20us; Peak Pulse Power Dissipation (Ppp)@10/1000us: 480W; Breakdown Voltage: 6V; Reverse Leakage Current (Ir): 500nA
U39 = CD4069_C3041279: Manufacturer: Slkor(萨科微); Add into BOM: yes; Supply Voltage(Single): 3V~15V; Supply Current (Max): 1uA; Number of Circuits: 6; Number of Inputs: 1
U41 U43 = DBT30R-7.62-2P-BK-P: Manufacturer: DORABO(地博电气); Add into BOM: yes; Barrier Type: 2-Side; Pitch: 7.62mm; Number of Positions or Pins: 1x2P; Number of PINs Per Row: 2; Current Rating: 17.5A; Voltage Rating (Max): 450V; Wire Gauge - AWG: 14~22; Wire Gauge - mm2: 1.5
U42 U44 = MAX6675ISA+T: Manufacturer: ADI(亚德诺)/MAXIM(美信); Add into BOM: yes; Resolution: 12; Voltage - Supply: 3V~5.5V; Interface Type: SPI; Chip Type Parameters/Description: Thermocouple to Digital Converter
VIB = KF2EDGSR-3.5-2*6P: Manufacturer: KEFA(科发); Add into BOM: yes; Connector Type: Receptacle-Close; Structure: 2x6P; Pitch: 3.5mm; Number of PINs Per Row: 6; Current Rating (Max): 10A; Voltage Rating (Max): 300V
